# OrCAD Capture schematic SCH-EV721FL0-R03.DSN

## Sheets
1 Block Diagram
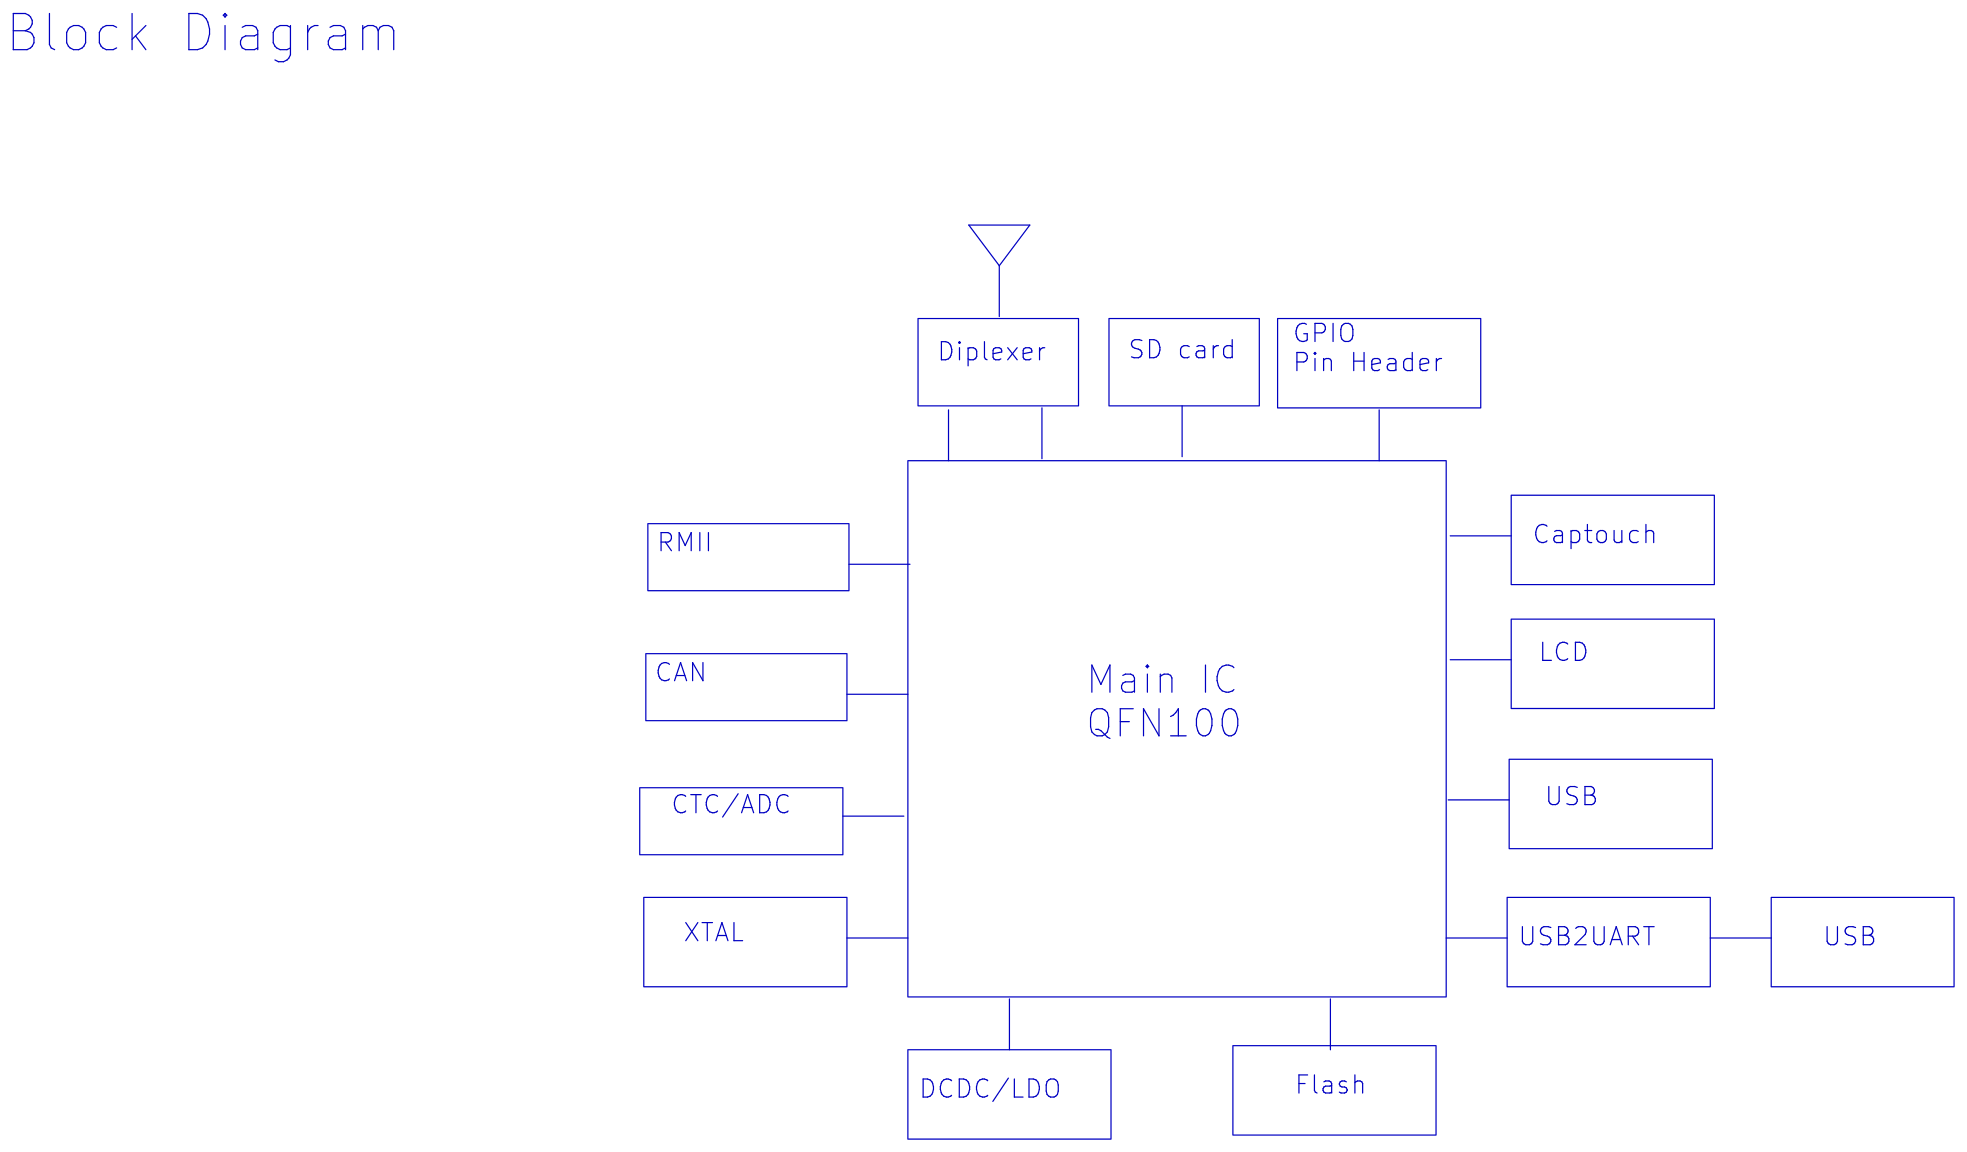
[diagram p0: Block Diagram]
2 Power Tree: title: G2; rev: 1.0; note: <>
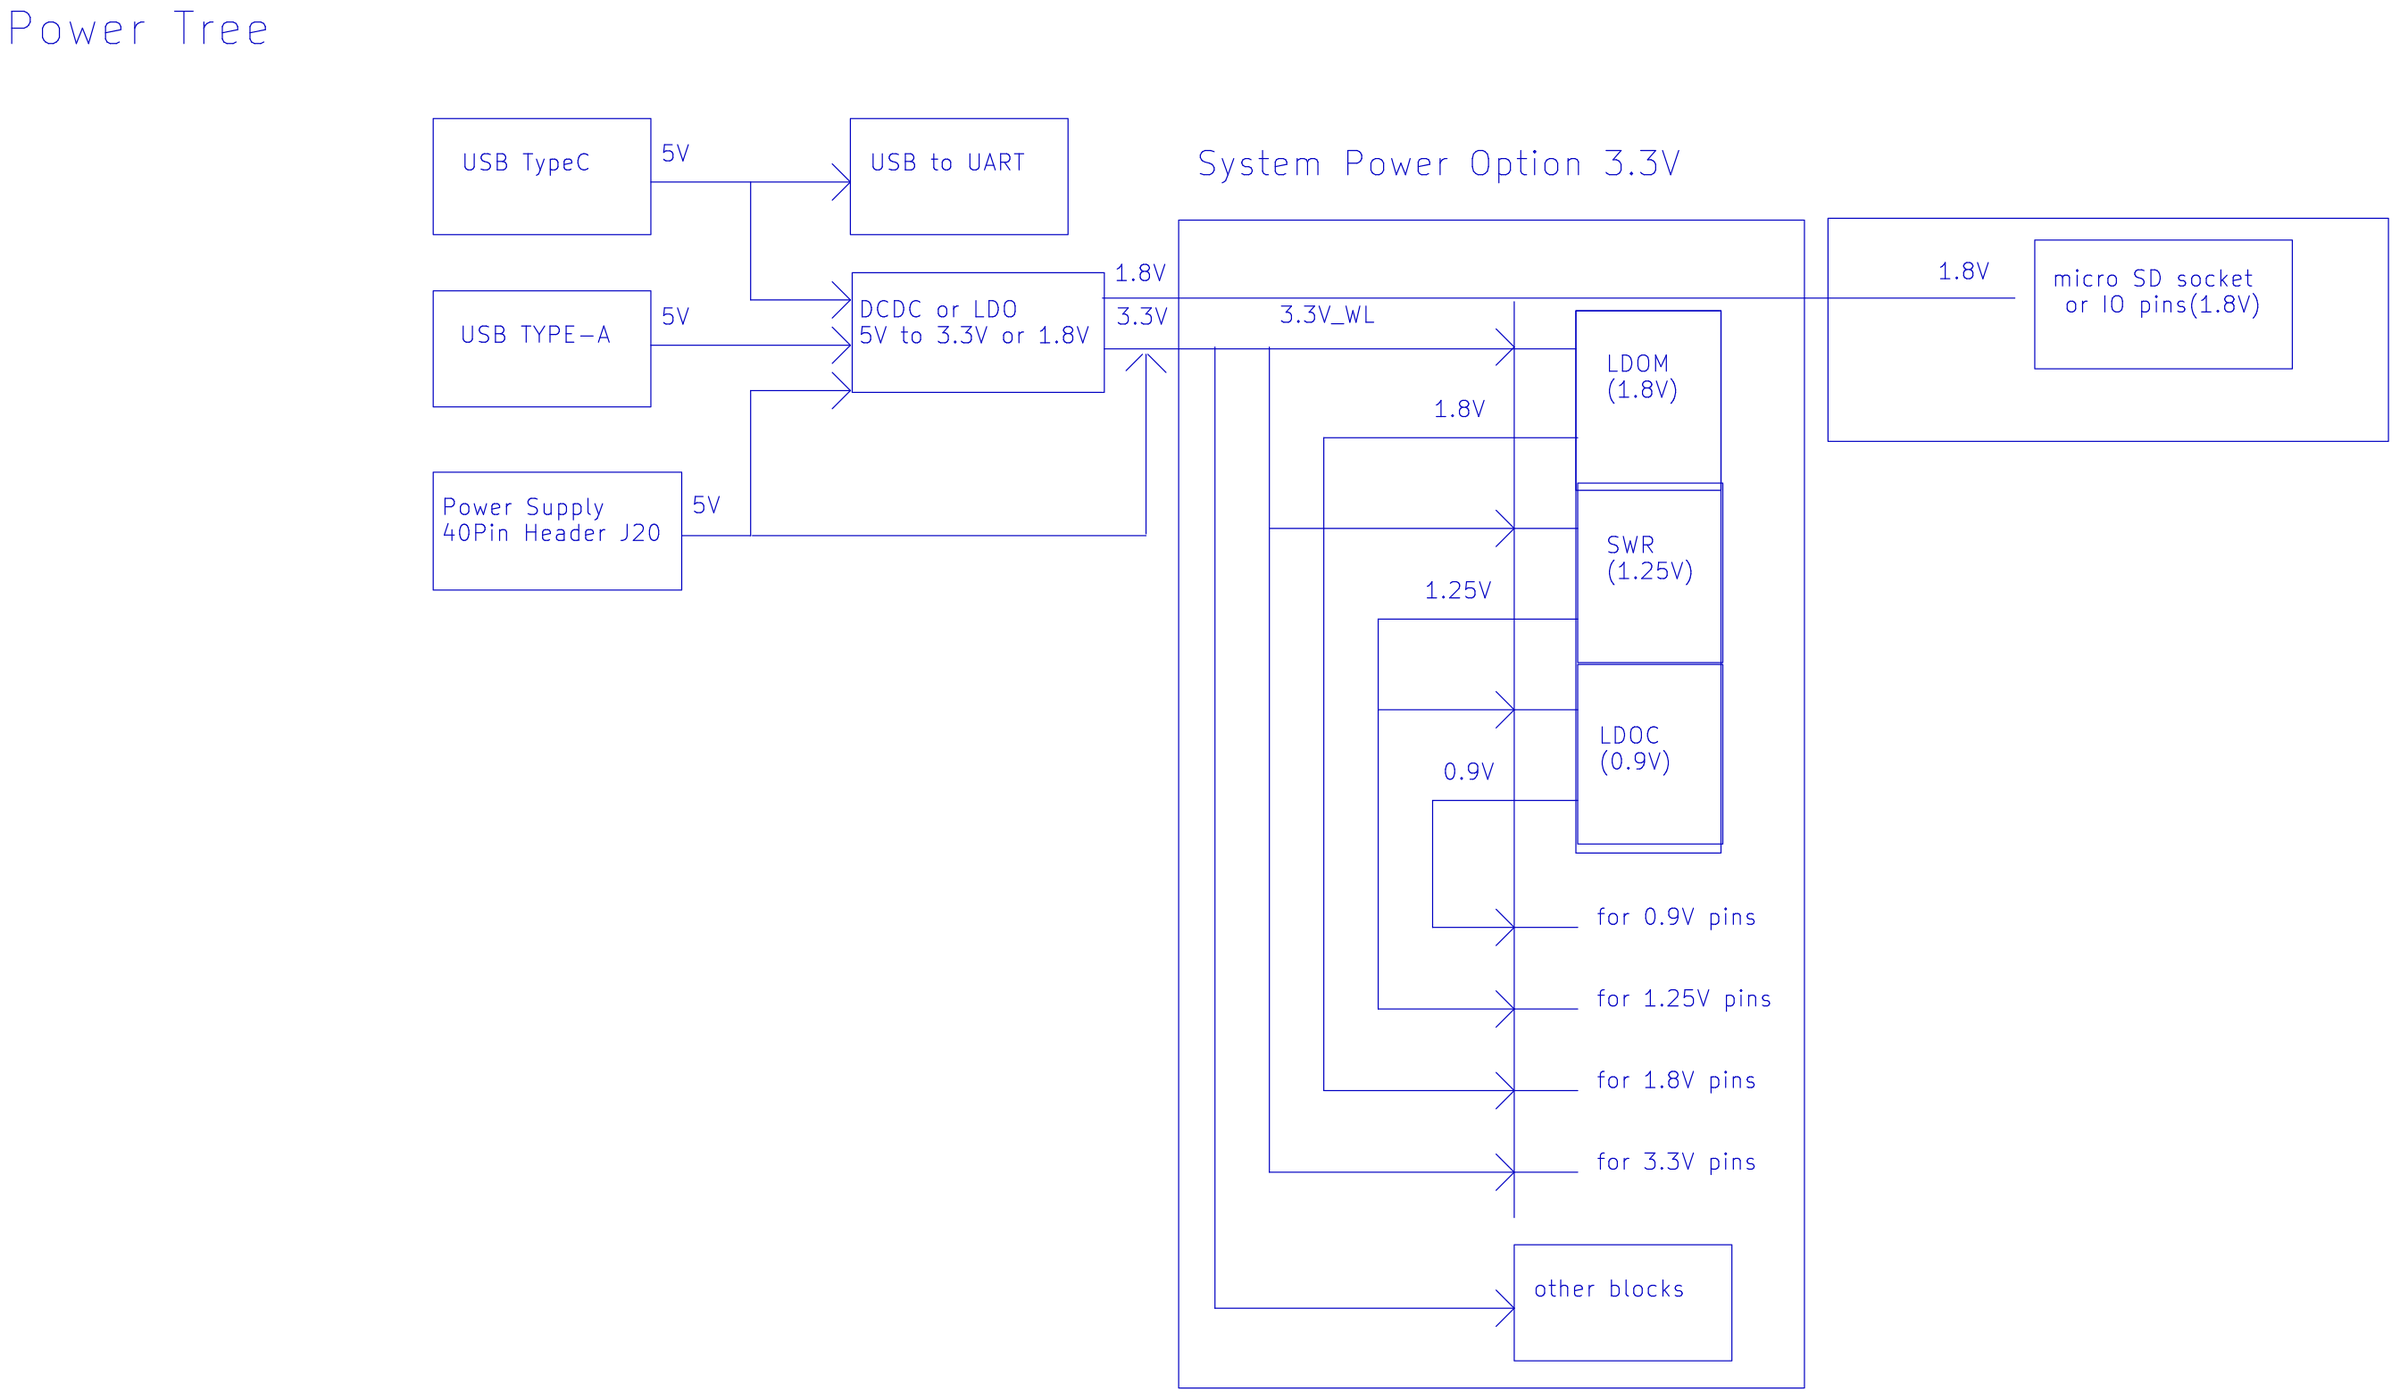
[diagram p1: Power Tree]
3 Power and USB2UART: size Custom; title: G2; rev: 1.0; note: <>
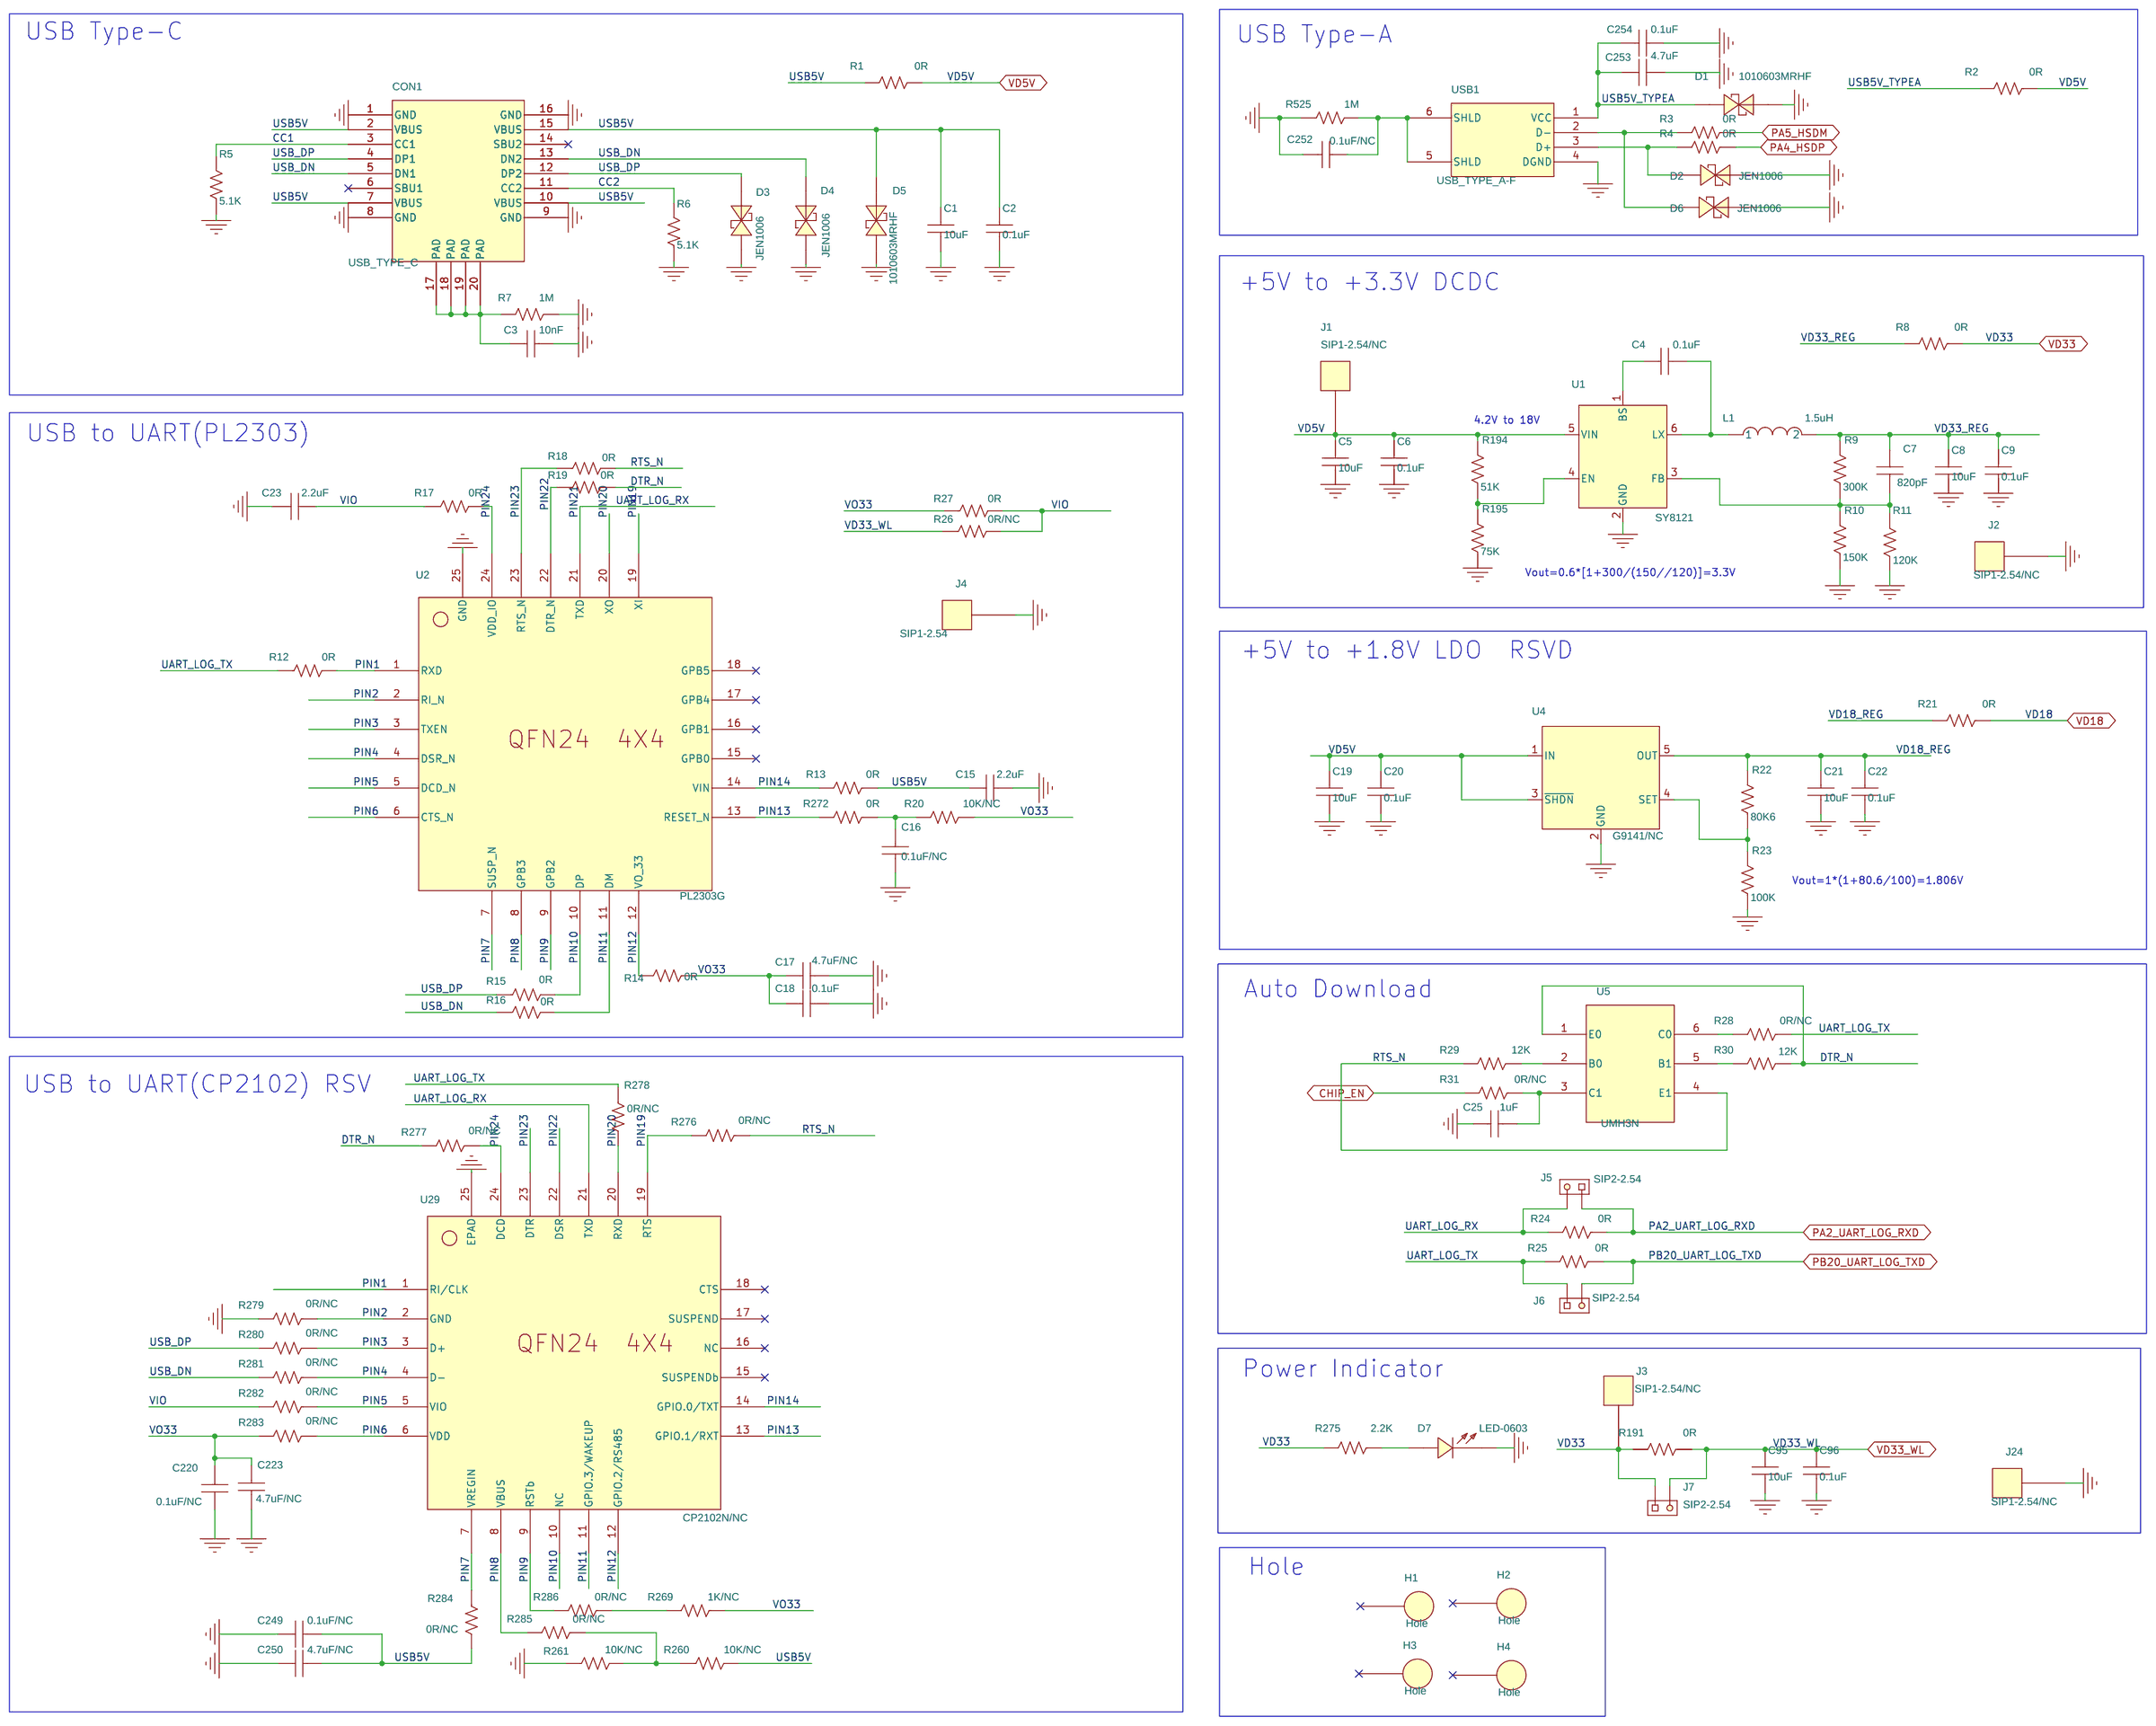
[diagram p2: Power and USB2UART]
4 Main Chip: size Custom; title: G2; rev: 1.0; note: <>
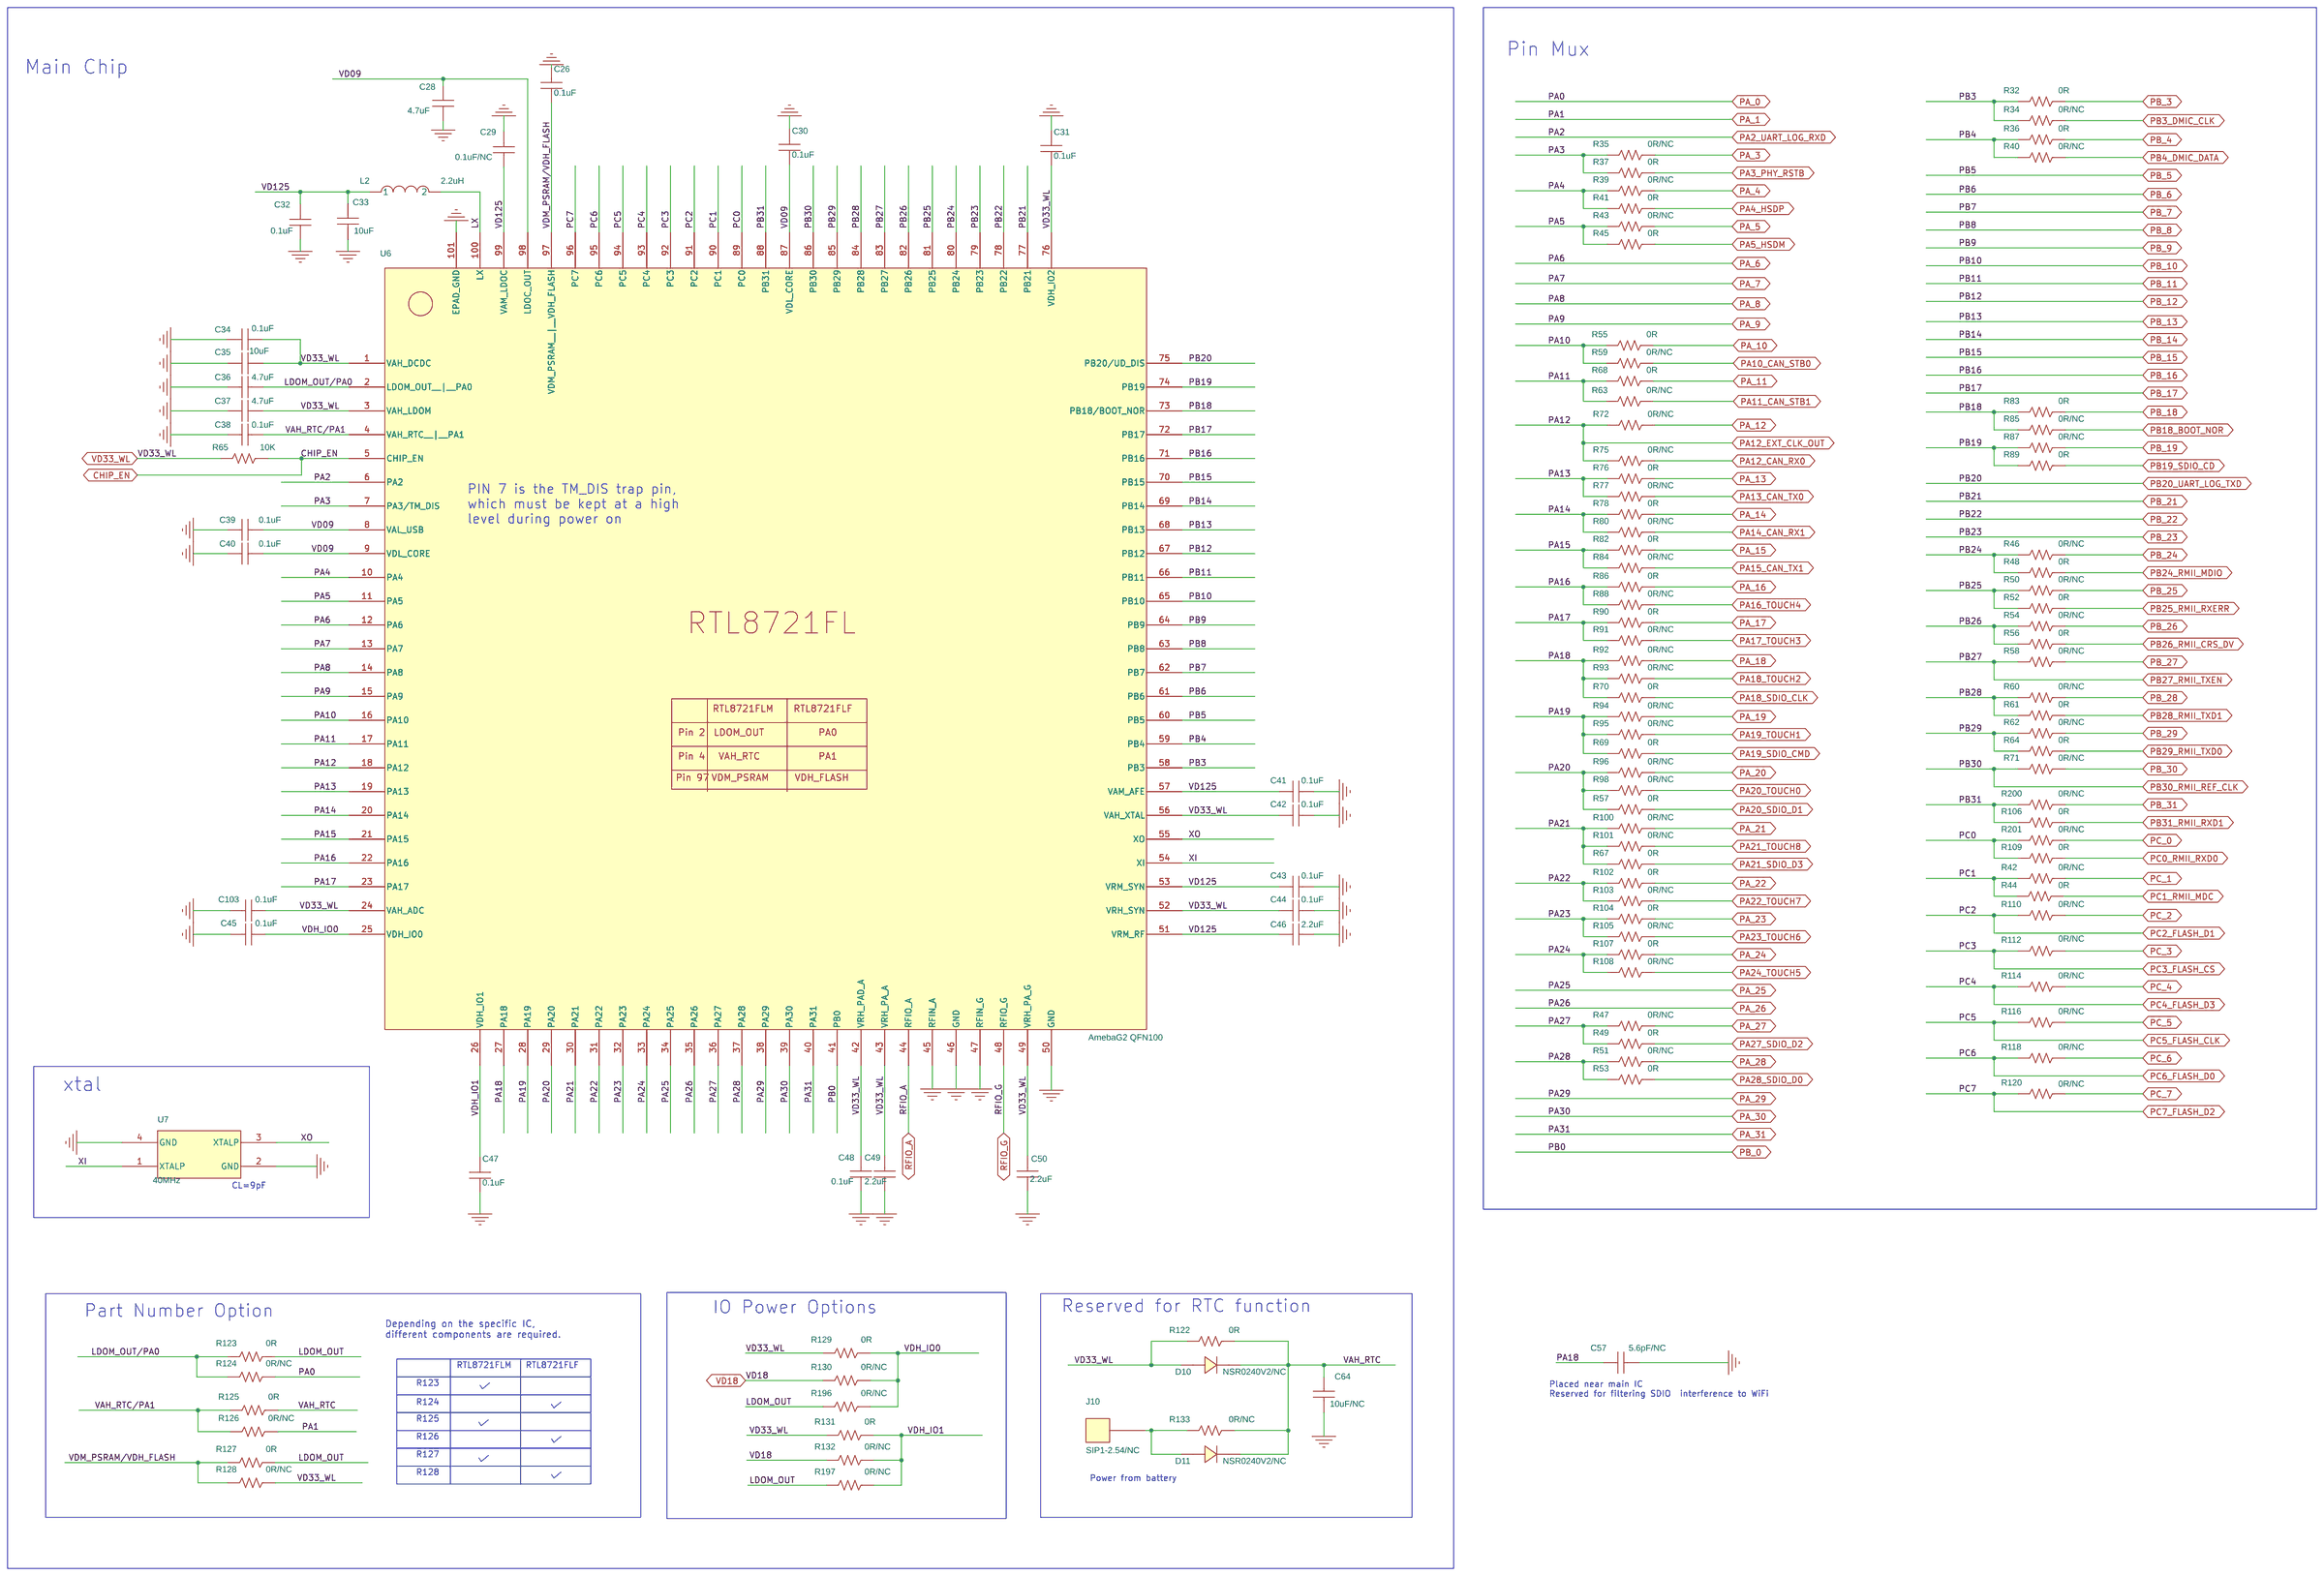
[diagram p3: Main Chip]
5 RF: size B; title: EV721DG0; rev: 1.0; note: <>
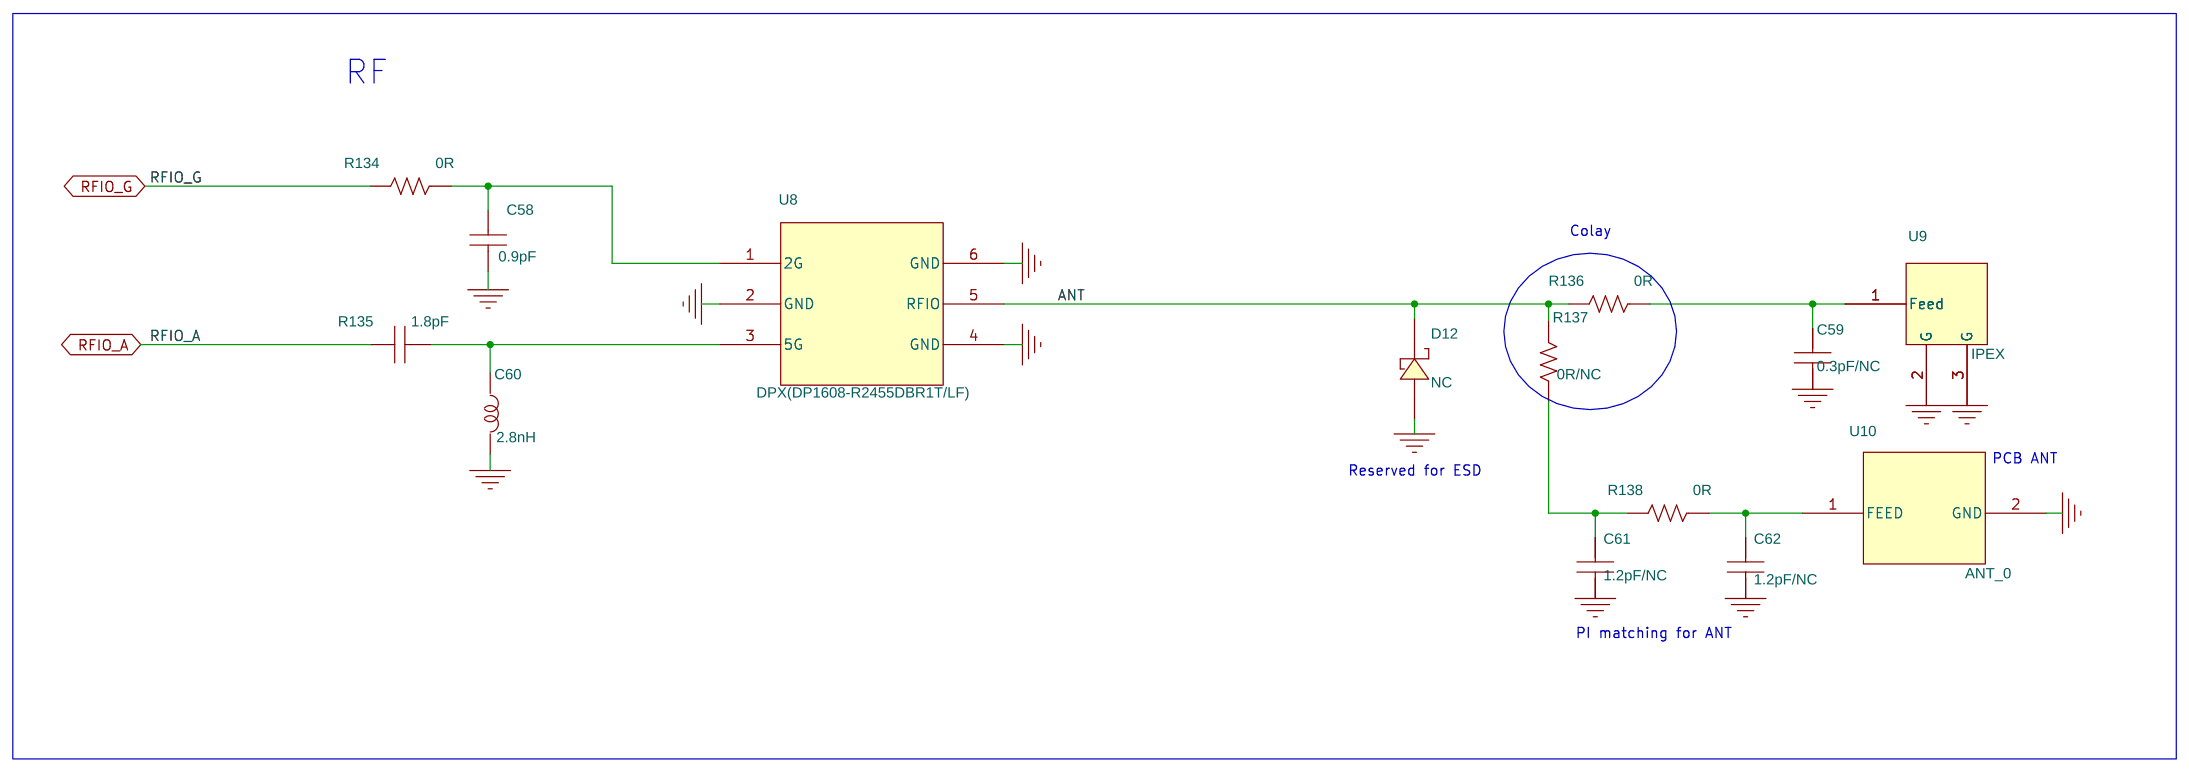
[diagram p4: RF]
6 Ethernet: size B
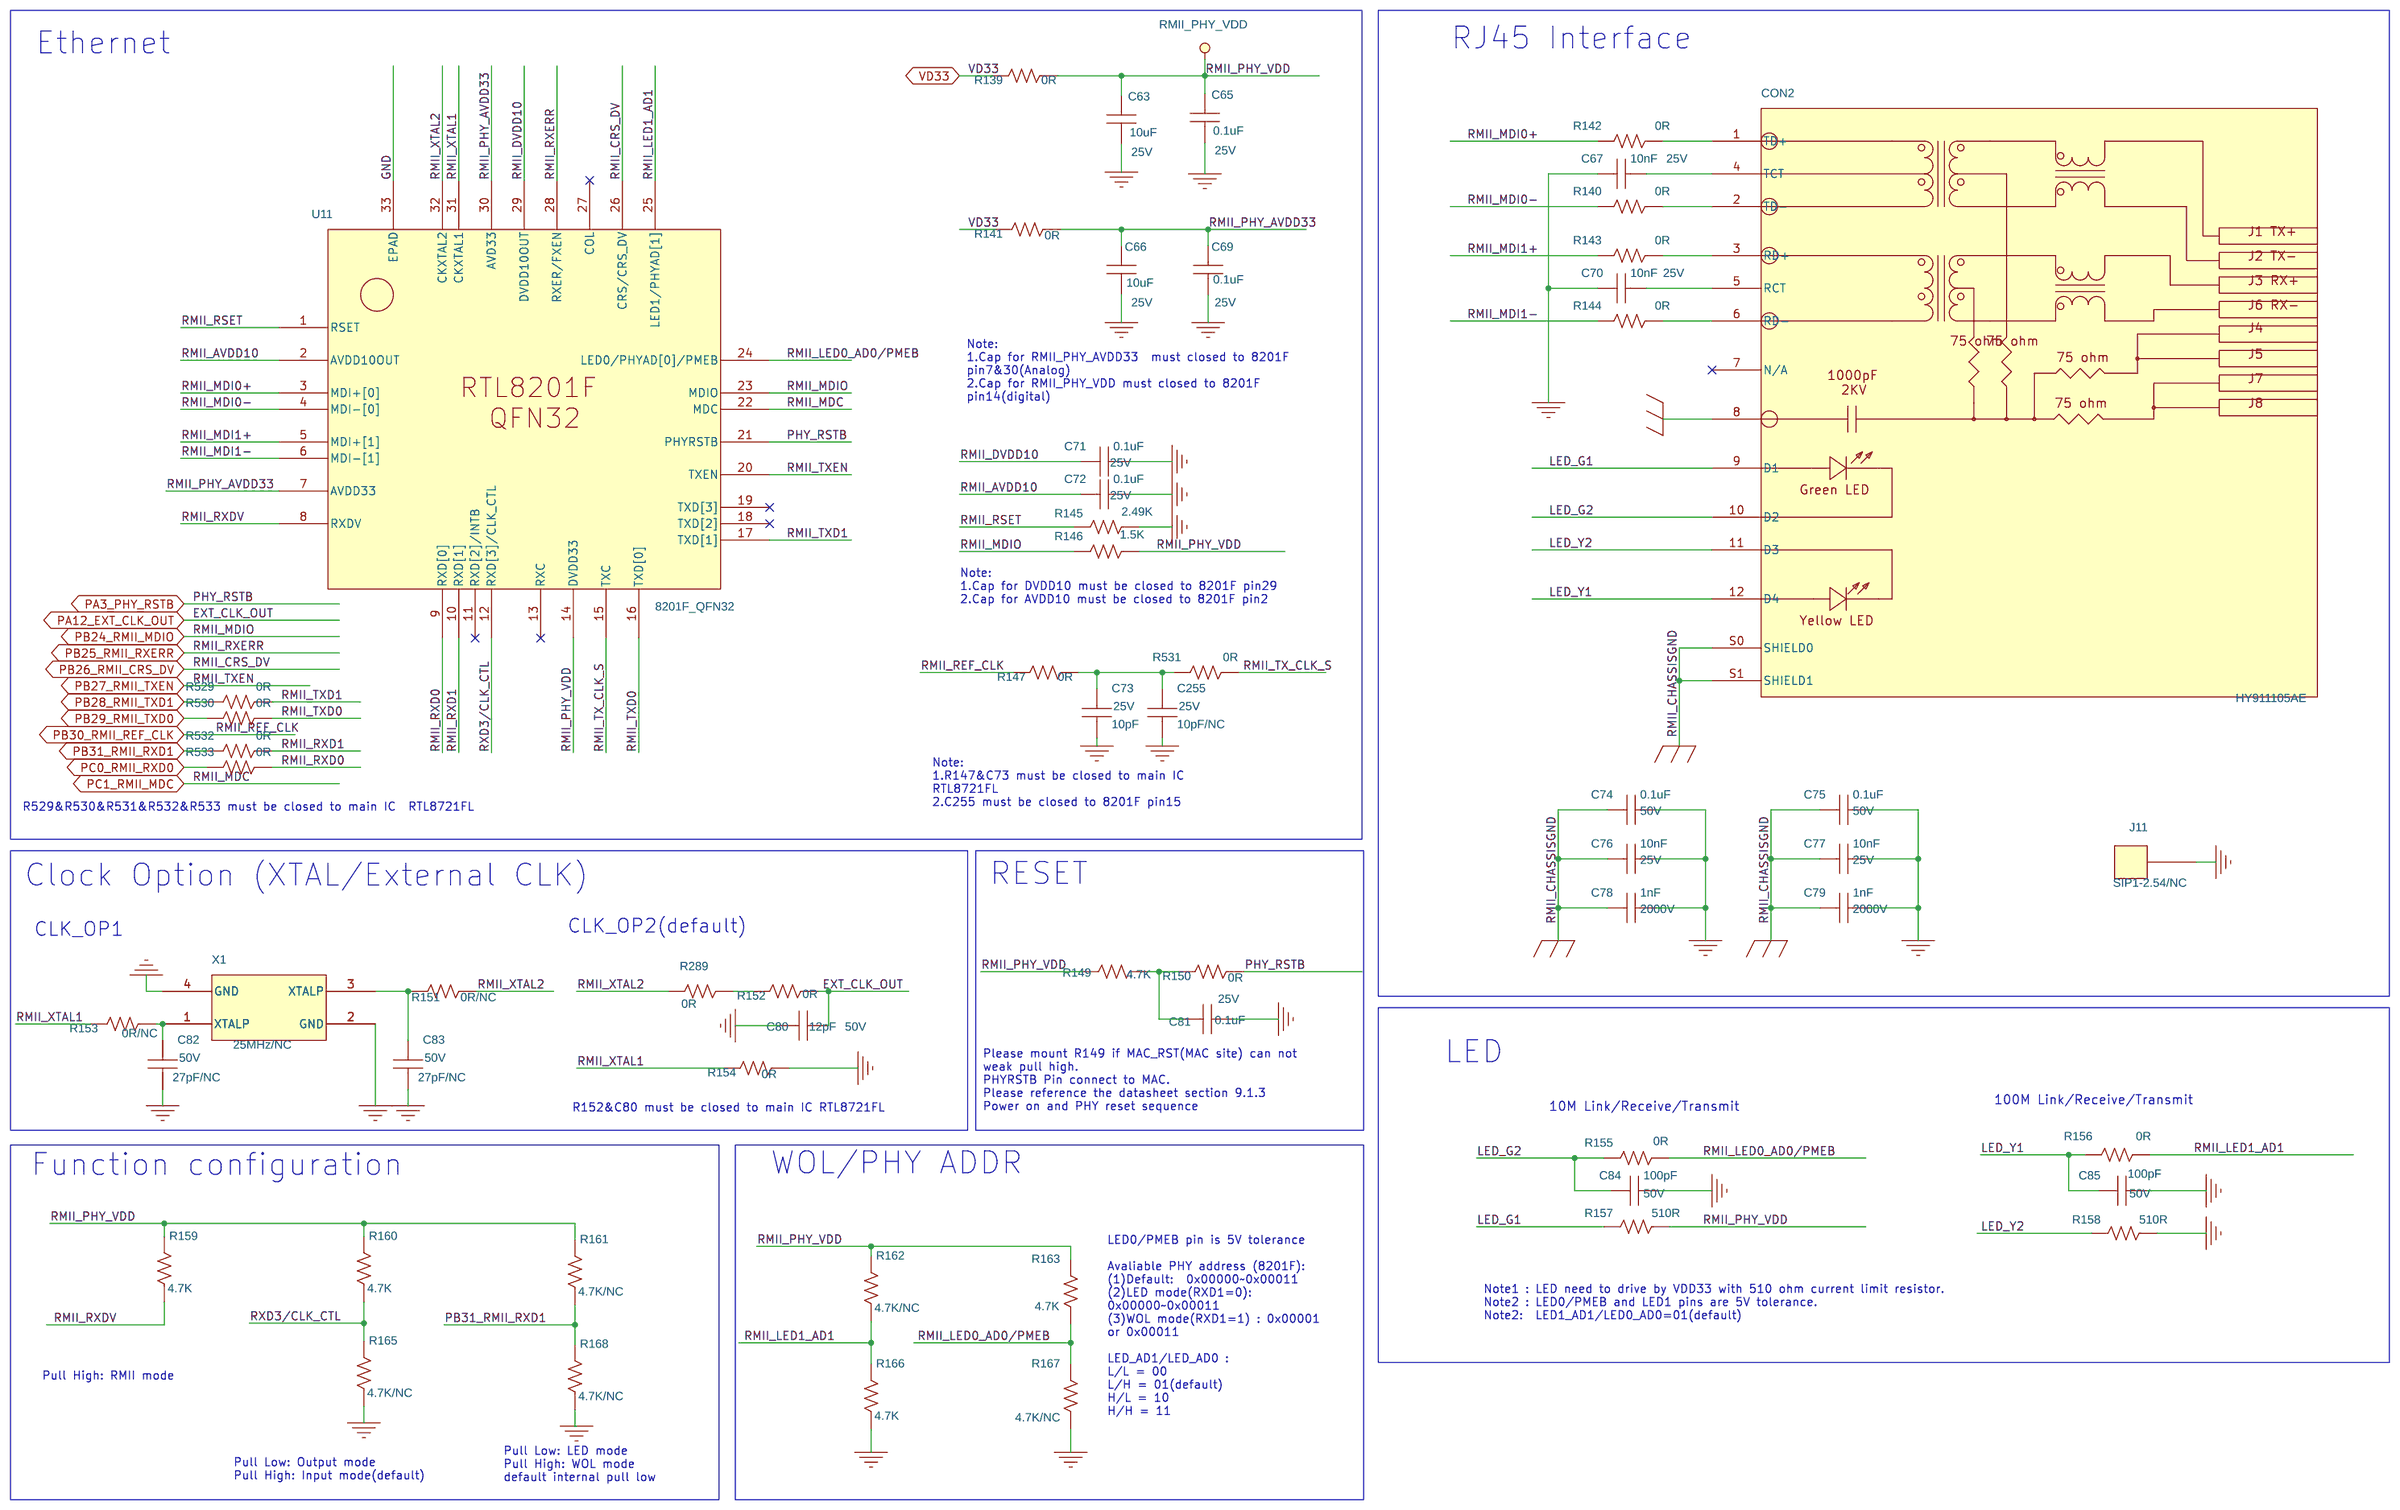
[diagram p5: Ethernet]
7 Function Block: size B; title: G2; rev: 1.0; note: <>
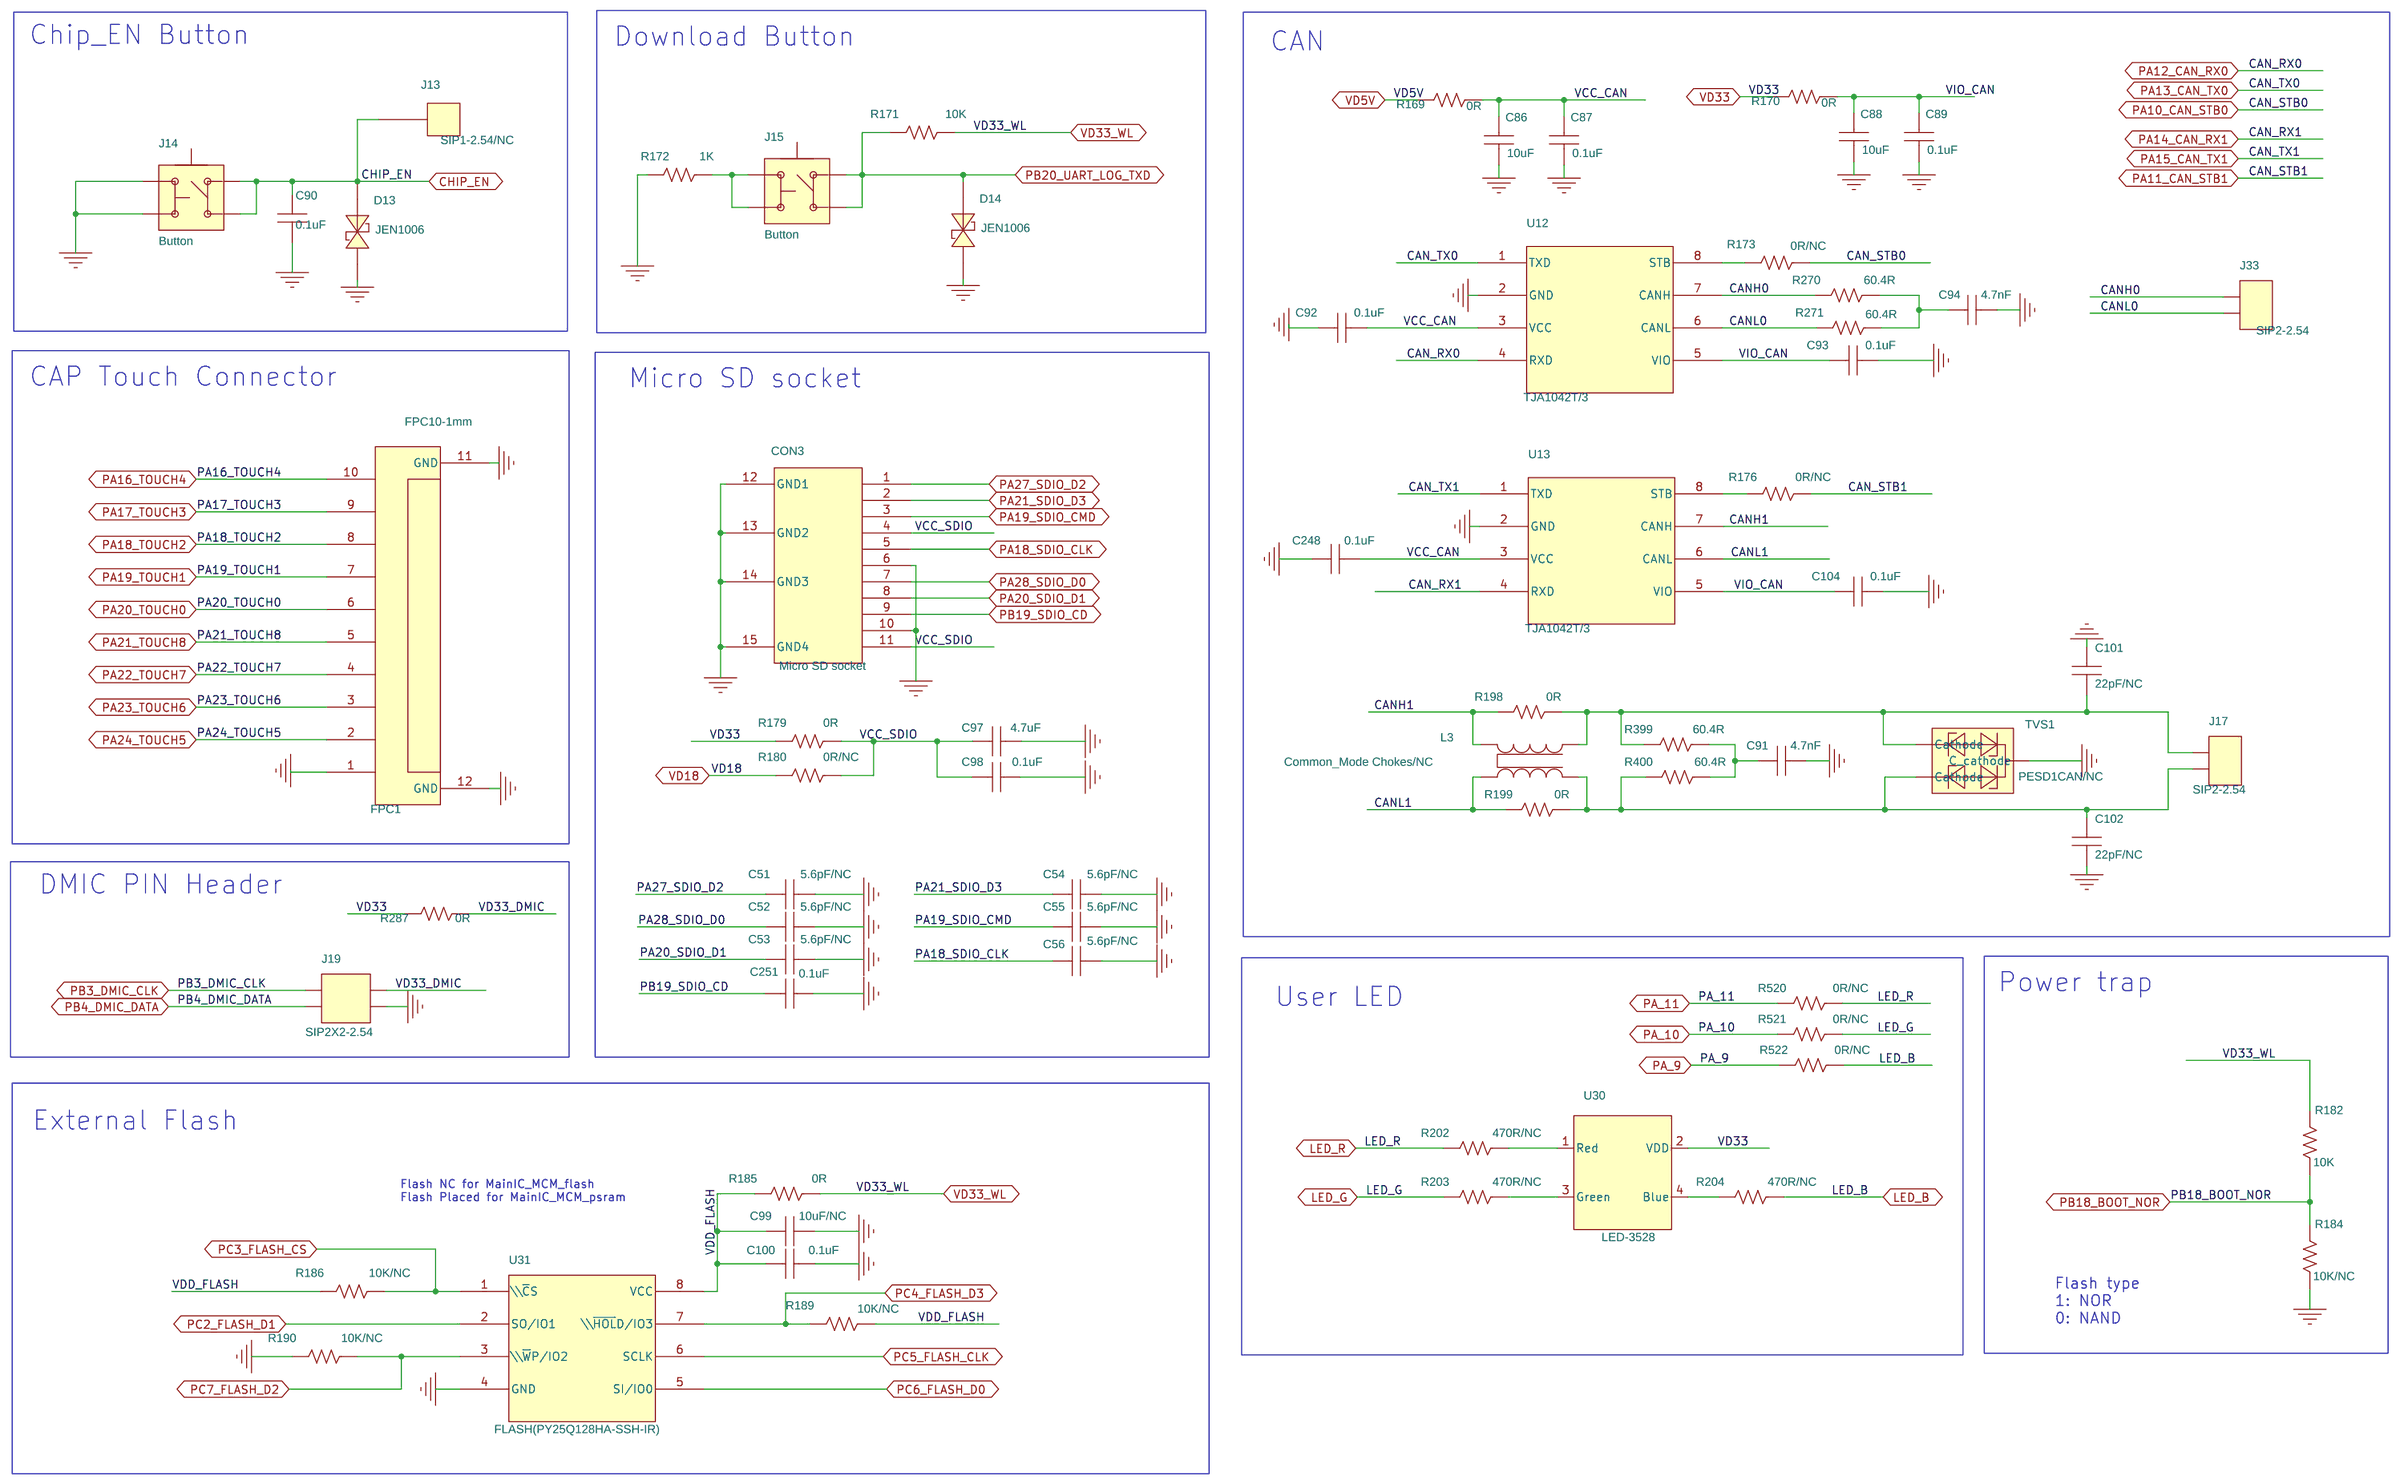
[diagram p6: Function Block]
8 Pin Header: size A; title: G2; rev: 1.0; note: <>
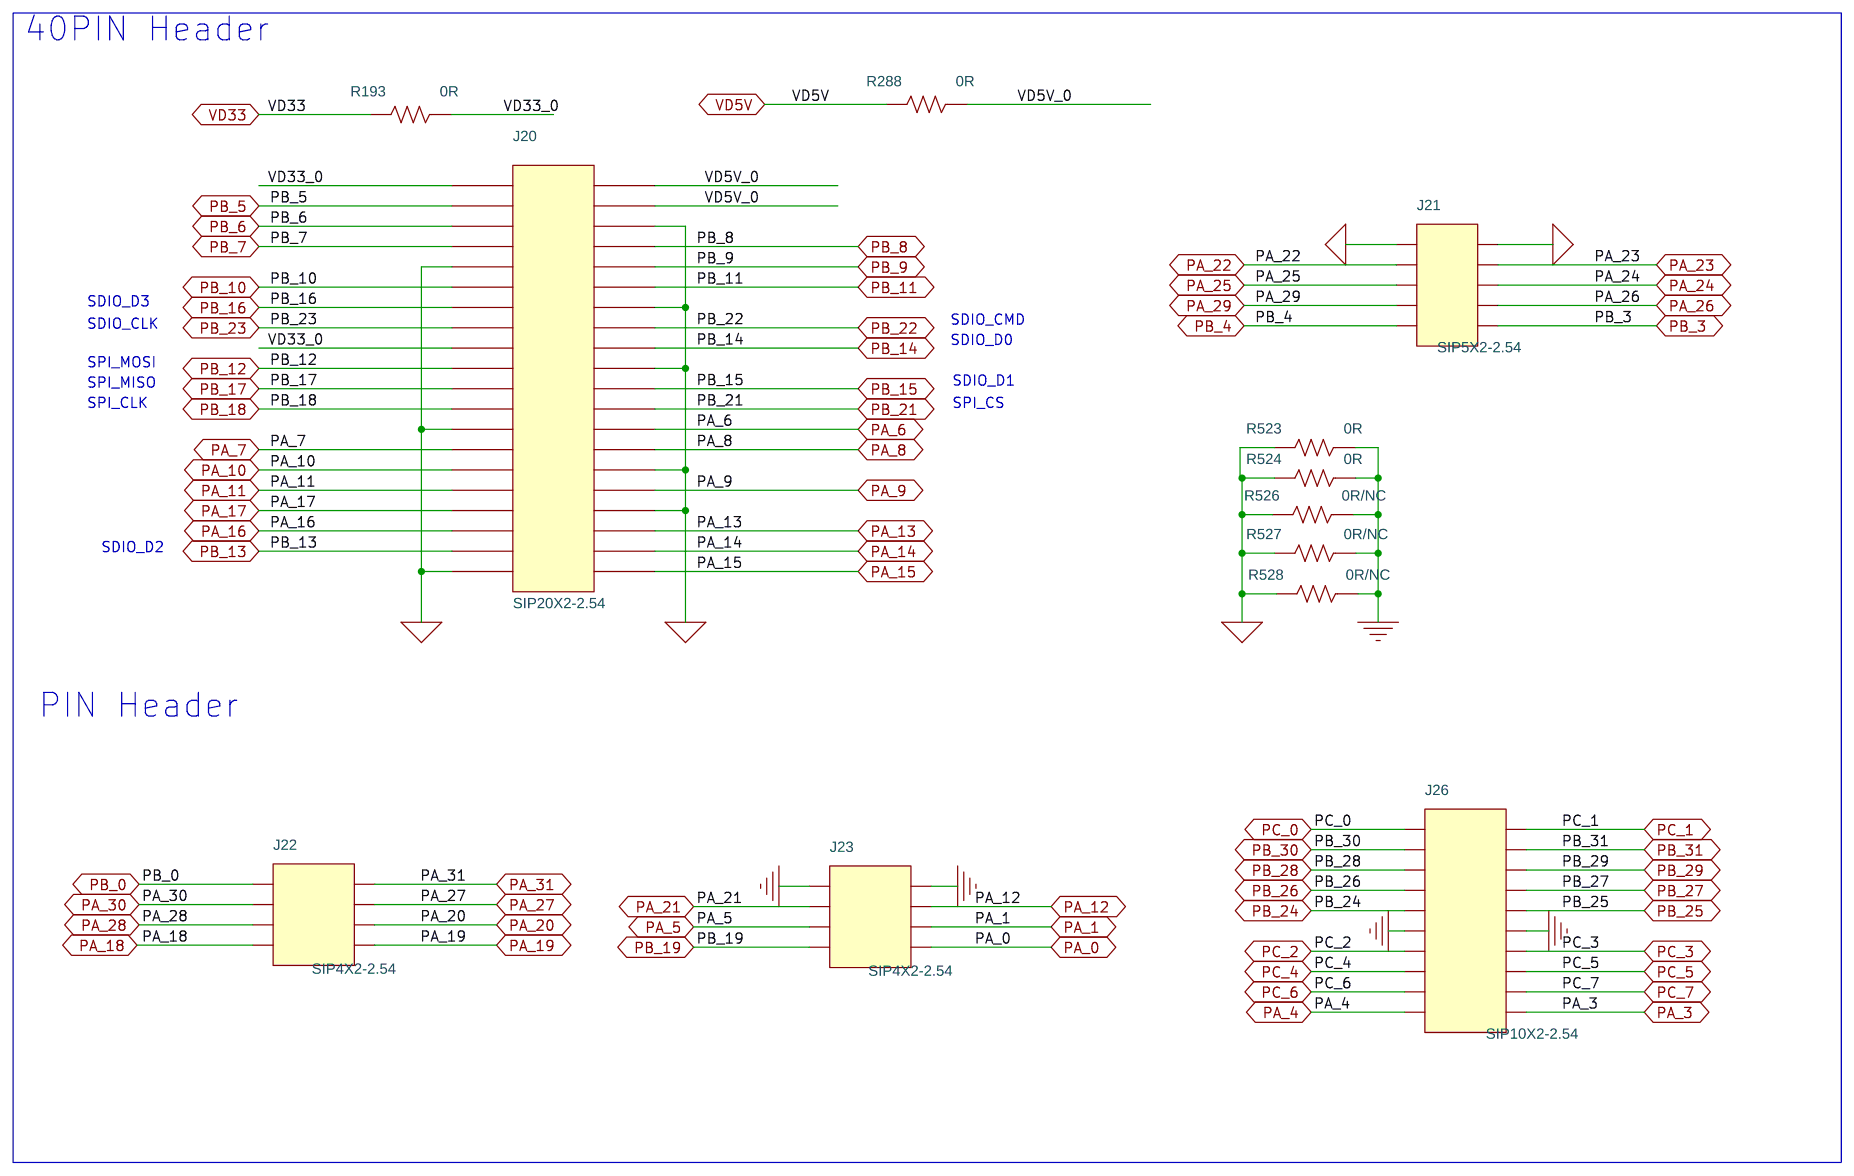
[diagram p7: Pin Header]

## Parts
sheet Ethernet
C63  10uF  [C0603]
C65  0.1uF  [C0201]
C66  10uF  [C0603]
C67  10nF  [C0402]
C69  0.1uF  [C0201]
C70  10nF  [C0402]
C71  0.1uF  [C0402]
C72  0.1uF  [C0402]
C73  10pF  [C0201]
C74  0.1uF  [C0603]
C75  0.1uF  [C0603]
C76  10nF  [C0402]
C77  10nF  [C0402]
C78  1nF  [C1206]
C79  1nF  [C1206]
C80  12pF  [C0402]
C81  0.1uF  [C0402]
C82  27pF/NC  [C0402]
C83  27pF/NC  [C0402]
C84  100pF  [C0402]
C85  100pF  [C0402]
C255  10pF/NC  [C0201]
CON2  HY911105AE  [RJ-45_1]
J11  SIP1-2.54/NC  [SIP1-2.54]
R139  0R  [R0402]
R140  0R  [R0201]
R141  0R  [R0402]
R142  0R  [R0201]
R143  0R  [R0201]
R144  0R  [R0201]
R145  2.49K  [R0402]
R146  1.5K  [R0402]
R147  0R  [R0402]
R149  4.7K  [R0402]
R150  0R  [R0402]
R151  0R/NC  [R0402]
R152  0R  [R0402]
R153  0R/NC  [R0402]
R154  0R  [R0402]
R155  0R  [R0402]
R156  0R  [R0402]
R157  510R  [R0402]
R158  510R  [R0402]
R159  4.7K  [R0402]
R160  4.7K  [R0402]
R161  4.7K/NC  [R0201]
R162  4.7K/NC  [R0402]
R163  4.7K  [R0402]
R165  4.7K/NC  [R0402]
R166  4.7K  [R0402]
R167  4.7K/NC  [R0402]
R168  4.7K/NC  [R0201]
R289  0R  [R0402]
R529  0R  [R0201]
R530  0R  [R0201]
R531  0R  [R0201]
R532  0R  [R0201]
R533  0R  [R0201]
U11  8201F_QFN32  [QFN32-0.5-5X5]
X1  25MHz/NC  [XTAL-3225]
sheet Function Block
C51  5.6pF/NC  [C0201]
C52  5.6pF/NC  [C0201]
C53  5.6pF/NC  [C0201]
C54  5.6pF/NC  [C0201]
C55  5.6pF/NC  [C0201]
C56  5.6pF/NC  [C0201]
C86  10uF  [C0603]
C87  0.1uF  [C0402]
C88  10uF  [C0603]
C89  0.1uF  [C0402]
C90  0.1uF  [C0402]
C91  4.7nF  [C0402]
C92  0.1uF  [C0402]
C93  0.1uF  [C0402]
C94  4.7nF  [C0402]
C97  4.7uF  [C0402]
C98  0.1uF  [C0402]
C99  10uF/NC  [C0402]
C100  0.1uF  [C0201]
C101  22pF/NC  [C0402]
C102  22pF/NC  [C0402]
C104  0.1uF  [C0402]
C248  0.1uF  [C0402]
C251  0.1uF  [C0201]
CON3  Micro SD socket  [SD_CARD15]
D13  JEN1006  [D0402-JEN]
D14  JEN1006  [D0402-JEN]
FPC1  FPC10-1mm  [FPC10-1]
J13  SIP1-2.54/NC  [SIP1-2.54]
J14  Button  [SW-4P-3X4]
J15  Button  [SW-4P-3X4]
J17  SIP2-2.54  [SIP2-2.54]
J19  SIP2X2-2.54  [SIP2X2-2.54]
J33  SIP2-2.54  [SIP2-2.54]
L3  Common_Mode Chokes/NC  [CMF5940]
R169  0R  [R0402]
R170  0R  [R0402]
R171  10K  [R0402]
R172  1K  [R0402]
R173  0R/NC  [R0402]
R176  0R/NC  [R0402]
R179  0R  [R0805]
R180  0R/NC  [R0805]
R182  10K  [R0402]
R184  10K/NC  [R0402]
R185  0R  [R0402]
R186  10K/NC  [R0201]
R189  10K/NC  [R0201]
R190  10K/NC  [R0201]
R198  0R  [R0402]
R199  0R  [R0402]
R202  470R/NC  [R0402]
R203  470R/NC  [R0402]
R204  470R/NC  [R0402]
R270  60.4R  [R0402]
R271  60.4R  [R0402]
R287  0R  [R0402]
R399  60.4R  [R0402]
R400  60.4R  [R0402]
R520  0R/NC  [R0402]
R521  0R/NC  [R0402]
R522  0R/NC  [R0402]
TVS1  PESD1CAN/NC  [SOT-23_MINI_S]
U12  TJA1042T/3  [SO8-150-4.9X3.9]
U13  TJA1042T/3  [SO8-150-4.9X3.9]
U30  LED-3528  [LED-3528]
U31  FLASH(PY25Q128HA-SSH-IR)  [WSON8-1.27-8X6-8pin]
sheet Main Chip
C26  0.1uF  [C0201]
C28  4.7uF  [C0402]
C29  0.1uF/NC  [C0201]
C30  0.1uF  [C0201]
C31  0.1uF  [C0201]
C32  0.1uF  [C0201]
C33  10uF  [C0402]
C34  0.1uF  [C0201]
C35  10uF  [C0402]
C36  4.7uF  [C0402]
C37  4.7uF  [C0402]
C38  0.1uF  [C0201]
C39  0.1uF  [C0201]
C40  0.1uF  [C0201]
C41  0.1uF  [C0201]
C42  0.1uF  [C0201]
C43  0.1uF  [C0201]
C44  0.1uF  [C0201]
C45  0.1uF  [C0201]
C46  2.2uF  [C0402]
C47  0.1uF  [C0201]
C48  0.1uF  [C0201]
C49  2.2uF  [C0402]
C50  2.2uF  [C0402]
C57  5.6pF/NC  [C0201]
C64  10uF/NC  [C0603]
C103  0.1uF  [C0201]
D10  NSR0240V2/NC  [SOD-X23]
D11  NSR0240V2/NC  [SOD-X23]
J10  SIP1-2.54/NC  [SIP1-2.54]
L2  2.2uH  [L2016]
R32  0R  [R0402]
R34  0R/NC  [R0402]
R35  0R/NC  [R0402]
R36  0R  [R0402]
R37  0R  [R0402]
R39  0R/NC  [R0402]
R40  0R/NC  [R0402]
R41  0R  [R0402]
R42  0R/NC  [R0402]
R43  0R/NC  [R0402]
R44  0R  [R0402]
R45  0R  [R0402]
R46  0R/NC  [R0402]
R47  0R/NC  [R0402]
R48  0R  [R0402]
R49  0R  [R0402]
R50  0R/NC  [R0402]
R51  0R/NC  [R0402]
R52  0R  [R0402]
R53  0R  [R0402]
R54  0R/NC  [R0402]
R55  0R  [R0402]
R56  0R  [R0402]
R57  0R  [R0402]
R58  0R/NC  [R0402]
R59  0R/NC  [R0402]
R60  0R/NC  [R0402]
R61  0R  [R0402]
R62  0R/NC  [R0402]
R63  0R/NC  [R0402]
R64  0R  [R0402]
R65  10K  [R0201]
R67  0R  [R0402]
R68  0R  [R0402]
R69  0R  [R0402]
R70  0R  [R0402]
R71  0R/NC  [R0402]
R72  0R/NC  [R0402]
R75  0R/NC  [R0402]
R76  0R  [R0402]
R77  0R/NC  [R0402]
R78  0R  [R0402]
R80  0R/NC  [R0402]
R82  0R  [R0402]
R83  0R  [R0402]
R84  0R/NC  [R0402]
R85  0R/NC  [R0402]
R86  0R  [R0402]
R87  0R/NC  [R0402]
R88  0R/NC  [R0402]
R89  0R  [R0402]
R90  0R  [R0402]
R91  0R/NC  [R0402]
R92  0R/NC  [R0402]
R93  0R/NC  [R0402]
R94  0R/NC  [R0402]
R95  0R/NC  [R0402]
R96  0R/NC  [R0402]
R98  0R/NC  [R0402]
R100  0R/NC  [R0402]
R101  0R/NC  [R0402]
R102  0R  [R0402]
R103  0R/NC  [R0402]
R104  0R  [R0402]
R105  0R/NC  [R0402]
R106  0R  [R0402]
R107  0R  [R0402]
R108  0R/NC  [R0402]
R109  0R  [R0402]
R110  0R/NC  [R0201]
R112  0R/NC  [R0201]
R114  0R/NC  [R0201]
R116  0R/NC  [R0201]
R118  0R/NC  [R0201]
R120  0R/NC  [R0201]
R122  0R  [R0402]
R123  0R  [R0201]
R124  0R/NC  [R0201]
R125  0R  [R0201]
R126  0R/NC  [R0201]
R127  0R  [R0201]
R128  0R/NC  [R0201]
R129  0R  [R0201]
R130  0R/NC  [R0201]
R131  0R  [R0201]
R132  0R/NC  [R0201]
R133  0R/NC  [R0402]
R196  0R/NC  [R0201]
R197  0R/NC  [R0201]
R200  0R/NC  [R0402]
R201  0R/NC  [R0402]
U6  AmebaG2 QFN100  [QFN100-0.35-10X10-EP6.1]
U7  40MHz  [XTAL-2016]
sheet Pin Header
J20  SIP20X2-2.54  [SIP20X2-2.54]
J21  SIP5X2-2.54  [SIP5X2-2.54]
J22  SIP4X2-2.54  [SIP4X2-2.54]
J23  SIP4X2-2.54  [SIP4X2-2.54]
J26  SIP10X2-2.54  [SIP10X2-2.54]
R193  0R  [R0805]
R288  0R  [R0805]
R523  0R  [R0402]
R524  0R  [R0402]
R526  0R/NC  [R0402]
R527  0R/NC  [R0402]
R528  0R/NC  [R0402]
sheet Power and USB2UART
C1  10uF  [C0603]
C2  0.1uF  [C0402]
C3  10nF  [C0402]
C4  0.1uF  [C0402]
C5  10uF  [C0603]
C6  0.1uF  [C0402]
C7  820pF  [C0402]
C8  10uF  [C0603]
C9  0.1uF  [C0402]
C15  2.2uF  [C0402]
C16  0.1uF/NC  [C0402]
C17  4.7uF/NC  [C0402]
C18  0.1uF  [C0402]
C19  10uF  [C0603]
C20  0.1uF  [C0402]
C21  10uF  [C0603]
C22  0.1uF  [C0402]
C23  2.2uF  [C0402]
C25  1uF  [C0402]
C95  10uF  [C0603]
C96  0.1uF  [C0402]
C220  0.1uF/NC  [C0402]
C223  4.7uF/NC  [C0402]
C249  0.1uF/NC  [C0402]
C250  4.7uF/NC  [C0402]
C252  0.1uF/NC  [C0402]
C253  4.7uF  [C0402]
C254  0.1uF  [C0402]
CON1  USB_TYPE_C  [USB-TYPEC-12P-SMD]
D1  1010603MRHF  [D0603-PGB]
D2  JEN1006  [D0402-JEN]
D3  JEN1006  [D0402-JEN]
D4  JEN1006  [D0402-JEN]
D5  1010603MRHF  [D0603-PGB]
D6  JEN1006  [D0402-JEN]
D7  LED-0603  [LED-0603]
H1  Hole  [HOLE-2.7X6.0-NPTH]
H2  Hole  [HOLE-2.7X6.0-NPTH]
H3  Hole  [HOLE-2.7X6.0-NPTH]
H4  Hole  [HOLE-2.7X6.0-NPTH]
J1  SIP1-2.54/NC  [SIP1-2.54]
J2  SIP1-2.54/NC  [SIP1-2.54]
J3  SIP1-2.54/NC  [SIP1-2.54]
J4  SIP1-2.54  [SIP1-2.54]
J5  SIP2-2.54  [SIP2-2.54]
J6  SIP2-2.54  [SIP2-2.54]
J7  SIP2-2.54  [SIP2-2.54]
J24  SIP1-2.54/NC  [SIP1-2.54]
L1  1.5uH  [L4442]
R1  0R  [R0805]
R2  0R  [R0805]
R3  0R  [R0402]
R4  0R  [R0402]
R5  5.1K  [R0402]
R6  5.1K  [R0402]
R7  1M  [R0402]
R8  0R  [R0805]
R9  300K  [R0402]
R10  150K  [R0402]
R11  120K  [R0402]
R12  0R  [R0402]
R13  0R  [R0402]
R14  0R  [R0402]
R15  0R  [R0402]
R16  0R  [R0402]
R17  0R  [R0402]
R18  0R  [R0402]
R19  0R  [R0402]
R20  10K/NC  [R0402]
R21  0R  [R0805]
R22  80K6  [R0402]
R23  100K  [R0402]
R24  0R  [R0402]
R25  0R  [R0402]
R26  0R/NC  [R0402]
R27  0R  [R0402]
R28  0R/NC  [R0402]
R29  12K  [R0402]
R30  12K  [R0402]
R31  0R/NC  [R0402]
R191  0R  [R0805]
R194  51K  [R0402]
R195  75K  [R0402]
R260  10K/NC  [R0402]
R261  10K/NC  [R0402]
R269  1K/NC  [R0402]
R272  0R  [R0402]
R275  2.2K  [R0402]
R276  0R/NC  [R0402]
R277  0R/NC  [R0402]
R278  0R/NC  [R0402]
R279  0R/NC  [R0402]
R280  0R/NC  [R0402]
R281  0R/NC  [R0402]
R282  0R/NC  [R0402]
R283  0R/NC  [R0402]
R284  0R/NC  [R0402]
R285  0R/NC  [R0402]
R286  0R/NC  [R0402]
R525  1M  [R0402]
U1  SY8121  [SOT-23-6]
U2  PL2303G  [UQFN24-0.5-4X4-EP1.5X1.5]
U4  G9141/NC  [SOT-23-5]
U5  UMH3N  [SOT-363-1.6]
U29  CP2102N/NC  [UQFN24-0.5-4X4-EP1.5X1.5]
USB1  USB_TYPE_A-F  [USB-TYPEA-4P-F]
sheet RF
C58  0.9pF  [C0201]
C59  0.3pF/NC  [C0201]
C60  2.8nH  [L0201]
C61  1.2pF/NC  [C0201]
C62  1.2pF/NC  [C0201]
D12  NC  [C0201]
R134  0R  [R0201]
R135  1.8pF  [C0201]
R136  0R  [R0201]
R137  0R/NC  [R0201]
R138  0R  [R0201]
U8  DPX(DP1608-R2455DBR1T/LF)  [DPX1608-6-0.5-0.25X0.6]
U9  IPEX  [IPEX3-1.35-0.7X2.2]
U10  ANT_0  [AMEBADPLUS_BGA100_EVB_ANT]

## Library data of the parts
C63 C66 C86 C88 = CAPACITOR_NON-POL_0: ±10%,25V,X5R; Manufacturer: WALSIN; Part Number: 0603X106K250CT; Voltage: 25V; Datasheet: \\172.29.17.1\cn\WLAN\WLAN2\boarddesignLIB\55_component_database\Datasheet\Capacitor\Capacitor_Walsin_MLCC.pdf
C65 C69 = CAPACITOR_NON-POL_0: ±10%,25V,X5R; Manufacturer: WALSIN; Part Number: 0201X104K250CT; Voltage: 25V; Datasheet: \\172.29.17.1\cn\WLAN\WLAN2\boarddesignLIB\05_component_database\Datasheet\Capacitor\Capacitor_Walsin_MLCC.pdf
C3 C67 C70 C76 C77 = CAPACITOR_NON-POL_0: ±10%,25V,X7R; Manufacturer: WALSIN; Part Number: 0402B103K250CT; Voltage: 25V; Datasheet: \\172.29.17.1\cn\WLAN\WLAN2\boarddesignLIB\50_component_database\Datasheet\Capacitor\Capacitor_Walsin_MLCC.pdf
C71 C72 C81 C87 C89 C92 C93 C104 C248 C252 C254 = CAPACITOR_NON-POL_0: ±10%,25V,X7R; Manufacturer: WALSIN; Part Number: 0402B104K250CT; Voltage: 25V; Datasheet: \\172.29.17.1\cn\WLAN\WLAN2\boarddesignLIB\06_component_database\Datasheet\Capacitor\Capacitor_Walsin_MLCC.pdf
C73 C255 = CAPACITOR_NON-POL_0: ±5%,25V,NPO,Y; Manufacturer: WALSIN; Part Number: 0201N100J250CT; Voltage: 25V; Datasheet: \\172.29.17.1\cn\WLAN\WLAN2\boarddesignLIB\51_component_database\Datasheet\Capacitor\Capacitor_Walsin_MLCC.pdf
C74 C75 = CAPACITOR_NON-POL_0: ±10%,50V,X7R; Manufacturer: WALSIN; Part Number: 0603B104K500CT; Voltage: 50V; Datasheet: \\172.29.17.1\cn\WLAN\WLAN2\boarddesignLIB\08_component_database\Datasheet\Capacitor\Capacitor_Walsin_MLCC.pdf
C78 C79 = CAPACITOR_NON-POL_0: ±10%,2000V,X7R; Manufacturer: WALSIN; Part Number: 1206B102K202CT; Voltage: 2000V; Datasheet: \\172.29.17.1\cn\WLAN\WLAN2\boarddesignLIB\75_component_database\Datasheet\Capacitor\Capacitor_Walsin_MLCC.pdf
C80 = CAPACITOR_NON-POL_0: ±5%,50V,NPO; Manufacturer: WALSIN; Part Number: 0402N120J500CT; Voltage: 50V; Datasheet: \\172.29.17.1\cn\WLAN\WLAN2\boarddesignLIB\61_component_database\Datasheet\Capacitor\Capacitor_Walsin_MLCC.pdf
C82 C83 = CAPACITOR_NON-POL_0: ±5%,50V,NPO; Manufacturer: WALSIN; Part Number: 0402N270J500CT; Voltage: 50V; Datasheet: \\172.29.17.1\cn\WLAN\WLAN2\boarddesignLIB\123_component_database\Datasheet\Capacitor\Capacitor_Walsin_MLCC.pdf
C84 C85 = CAPACITOR_NON-POL_0: ±5%,50V,NPO; Manufacturer: WALSIN; Part Number: 0402N101J500CT; Voltage: 50V; Datasheet: \\172.29.17.1\cn\WLAN\WLAN2\boarddesignLIB\47_component_database\Datasheet\Capacitor\Capacitor_Walsin_MLCC.pdf
CON2 = RJ-45_1: 有灯，8数据脚，百兆网络变压器; Manufacturer: HCTL; Datasheet: \\172.29.17.1\cn\WLAN\WLAN2\boarddesignLIB\01_component_database\Datasheet\Connector\RJ45 Connector__HCTL_HC911105A-M305-A.pdf
J1-J4 J11 J13 J24 = CON1: Pin Header; Part Type: Pin Header
R139 R141 R147 R150-R156 R169 R170 R173 R176 R198 R199 R289 = RES_0: JUMPER; Manufacturer: WALSIN; Part Number: WR04X000PTL; Datasheet: \\172.29.17.1\cn\WLAN\WLAN2\boarddesignLIB\01_component_database\Datasheet\Resistor\Resistor_Walsin_chipR.pdf
R140 R142-R144 = RES_0: JUMPER; Manufacturer: WALSIN; Part Number: WR02X000PTL; Datasheet: \\172.29.17.1\cn\WLAN\WLAN2\boarddesignLIB\63_component_database\Datasheet\Resistor\Resistor_Walsin_chipR.pdf
R145 = RES_0: +/-1%; Manufacturer: WALSIN; Part Number: WR04X2491FTL; Datasheet: \\172.29.17.1\cn\WLAN\WLAN2\boarddesignLIB\01_component_database\Datasheet\Resistor\Resistor_Walsin_chipR.pdf
R146 = RES_0: +/-5%; Manufacturer: WALSIN; Part Number: WR04X152 JTL; Datasheet: \\172.29.17.1\cn\WLAN\WLAN2\boarddesignLIB\01_component_database\Datasheet\Resistor\Resistor_Walsin_chipR.pdf
R149 R159-R163 R165-R168 = RES_0: +/-1%; Manufacturer: WALSIN; Part Number: WR04X4701FTL; Datasheet: \\172.29.17.1\cn\WLAN\WLAN2\boarddesignLIB\01_component_database\Datasheet\Resistor\Resistor_Walsin_chipR.pdf
R157 R158 = RES_0: +/-1%; Manufacturer: WALSIN; Part Number: WR04X5100FTL; Datasheet: \\172.29.17.1\cn\WLAN\WLAN2\boarddesignLIB\01_component_database\Datasheet\Resistor\Resistor_Walsin_chipR.pdf
R110 R112 R114 R116 R118 R120 R529-R533 = RES_0: JUMPER; Manufacturer: WALSIN; Part Number: WR02X000PTL; Datasheet: \\172.29.17.1\cn\WLAN\WLAN2\boarddesignLIB\01_component_database\Datasheet\Resistor\Resistor_Walsin_chipR.pdf
U11 = RTL8201F_QFN32: Manufacturer: Realtek; Part Number: RTL8201F
X1 = XTAL_0: 16pF，40ohms，30ppm，-40-105度; Manufacturer: 加高; Part Number: E3SB25E000909E
C51-C57 = CAPACITOR_NON-POL_0: Part Number: RF03N5R6B250CT; Part Type: Ceramic; Tolerance,Voltage,Dielectric,Lead Free(Y/N): +/-0.1pF,25V,NPO,Y; Datasheet: \\172.29.17.1\cn\WLAN\WLAN2\boarddesignLIB\164_component_database\Datasheet\Capacitor\Capacitor_Walsin_MLCC.pdf
C2 C4 C6 C9 C16 C18 C20 C22 C90 C96 C98 C220 C249 = CAPACITOR_NON-POL_0: Part Number: 0402B104K250CT; Part Type: Ceramic; Tolerance,Voltage,Dielectric,Lead Free(Y/N): ±10%,25V X7R,; Datasheet: \\172.29.17.1\cn\WLAN\WLAN2\boarddesignLIB\06_component_database\Datasheet\Capacitor\Capacitor_Walsin_MLCC.pdf
C91 C94 = CAPACITOR_NON-POL_0: ±10%,50V,X7R; Manufacturer: WALSIN; Part Number: 0402B472K500CT; Voltage: 50V; Datasheet: \\172.29.17.1\cn\WLAN\WLAN2\boarddesignLIB\144_component_database\Datasheet\Capacitor\Capacitor_Walsin_MLCC.pdf
C17 C97 = CAPACITOR_NON-POL_0: Part Number: 0402X475M160CT; Part Type: Ceramic; Tolerance,Voltage,Dielectric,Lead Free(Y/N): ±20%,16V,X5R; Datasheet: \\172.29.17.1\cn\WLAN\WLAN2\boarddesignLIB\147_component_database\Datasheet\Capacitor\Capacitor_Walsin_MLCC.pdf
C99 = CAPACITOR_NON-POL_0: Part Number: 0402X106K160CT; Voltage: 16V; Datasheet: \\172.29.17.1\cn\WLAN\WLAN2\boarddesignLIB\54_component_database\Datasheet\Capacitor\Capacitor_Walsin_MLCC.pdf
C26 C29-C32 C34 C38-C45 C47 C48 C100 C103 C251 = CAPACITOR_NON-POL_0: Part Number: 0201X104K100CT; Part Type: Ceramic; Tolerance,Voltage,Dielectric,Lead Free(Y/N): ±10%，10V，X5R; Datasheet: \\172.29.17.1\cn\WLAN\WLAN2\boarddesignLIB\04_component_database\Datasheet\Capacitor\Capacitor_Walsin_MLCC.pdf
C101 C102 = CAPACITOR_NON-POL_0: ±5%,50V,NPO; Manufacturer: WALSIN; Part Number: 0402N220J500CT; Voltage: 50V; Datasheet: \\172.29.17.1\cn\WLAN\WLAN2\boarddesignLIB\112_component_database\Datasheet\Capacitor\Capacitor_Walsin_MLCC.pdf
CON3 = SD-TF21: SD Connector 15PIN; Part Number: SD-TF21-406-S157
D2-D4 D6 D13 D14 = Bi-directional_ESD_0: Bi-directional, 3.3V; Manufacturer: JDT Fuse; Part Number: JEN1006-3.3V-ULC; Datasheet: \\172.29.17.1\cn\WLAN\WLAN2\boarddesignLIB\01_component_database\Datasheet\TVS\TVS_JDTfuse_JEN1006-3.3V-ULC.pdf
FPC1 = FPC-10: 单排，1．0mm-10P.下接翻盖
J14 J15 = BUTTON_0: SMD, 4pin， -25℃ to 70℃; Part Number: TSA343G00-250DZY; Part Type: Tactile Switch; Datasheet: \\172.29.17.1\cn\WLAN\WLAN2\boarddesignLIB\01_component_database\Datasheet\Key-Switch\Key_Bright, TSA343G00-250DZY.pdf
J17 J33 = CON2: Pin Header
J19 = CON4A: Pin Header
L3 = Common_chokes_0: 4P,150℃; Manufacturer: TDK; Part Number: B82789C0/S0; Datasheet: \\172.29.17.1\cn\WLAN\WLAN2\boarddesignLIB\01_component_database\Datasheet\Bead-EMI Optimization\Common_mode_Chokes_TDK_ B82789C0.pdf
R171 = RES_0: Part Number: WR04X1002 FTL; Part type: Chip Resistor; Tolerance,Voltage,Dielectric,Lead Free(Y/N): +/-1%; Datasheet: \\172.29.17.1\cn\WLAN\WLAN2\boarddesignLIB\190_component_database\Datasheet\ResistorResistor_Walsin, chipR.pdf
R172 = RES_0: Part Number: WR04X1001FTL; Part type: Chip Resistor; Tolerance,Voltage,Dielectric,Lead Free(Y/N): +/-1%; Datasheet: \\172.29.17.1\cn\WLAN\WLAN2\boarddesignLIB\153_component_database\Datasheet\ResistorResistor_Walsin, chipR.pdf
R1 R2 R8 R21 R179 R180 R191 R193 R288 = RES_0: Part Number: WR08X000PTL; Part type: Chip Resistor; Tolerance,Voltage,Dielectric,Lead Free(Y/N): JUMPER; Datasheet: \\172.29.17.1\cn\WLAN\WLAN2\boarddesignLIB\65_component_database\Datasheet\ResistorResistor_Walsin_chipR.pdf
R182 R184 = RES_0: Part Number: WR04X1002 FTL; Part type: Chip Resistor; Tolerance,Voltage,Dielectric,Lead Free(Y/N): +/-1%; Datasheet: \\172.29.17.1\cn\WLAN\WLAN2\boarddesignLIB\191_component_database\Datasheet\Resistor\Resistor_Walsin_chipR.pdf
R122 R133 R185 R287 = RES_0: Part Number: WR04X000PTL; Tolerance,Voltage,Dielectric,Lead Free(Y/N): JUMPER; Datasheet: \\172.29.17.1\cn\WLAN\WLAN2\boarddesignLIB\64_component_database\Datasheet\Resistor\Resistor_Walsin_chipR.pdf
R186 R189 R190 = RES_0: Part Number: WR02X103 JAL; Tolerance,Voltage,Dielectric,Lead Free(Y/N): +/-5%; Datasheet: \\172.29.17.1\cn\WLAN\WLAN2\boarddesignLIB\40_component_database\Datasheet\Resistor\Resistor_Walsin_chipR.pdf
R202-R204 = RES_0: Part Number: WR04X471 JTL; Tolerance,Voltage,Dielectric,Lead Free(Y/N): +/-5%; Datasheet: \\172.29.17.1\cn\WLAN\WLAN2\boarddesignLIB\141_component_database\Datasheet\Resistor\Resistor_Walsin_chipR.pdf
R270 R271 R399 R400 = RES_0: +/-1%; Manufacturer: WALSIN; Part Number: WR04X60R4FTL; Datasheet: \\172.29.17.1\cn\WLAN\WLAN2\boarddesignLIB\01_component_database\Datasheet\Resistor\Resistor_Walsin_chipR.pdf
R3 R4 R12-R19 R24-R28 R31 R32 R34-R37 R39-R64 R67-R72 R75-R78 R80 R82-R96 R98 R100-R109 R200 R201 R272 R276-R286 R520-R524 R526-R528 = RES_0: Part Number: WR04X000PTL; Part type: Chip Resistor; Tolerance,Voltage,Dielectric,Lead Free(Y/N): JUMPER; Datasheet: \\172.29.17.1\cn\WLAN\WLAN2\boarddesignLIB\63_component_database\Datasheet\ResistorResistor_Walsin_chipR.pdf
TVS1 = CAN_ESD_0: 23Kv, Can bus ESD; Manufacturer: Nexperia; Part Number: PESD1CAN; Datasheet: \\172.29.17.1\cn\WLAN\WLAN2\boarddesignLIB\01_component_database\Datasheet\TVS\ESD_Nexperia_PESD1CAN.pdf
U12 U13 = CAN_trans_0: ±8Kv; Datasheet: \\172.29.17.1\cn\WLAN\WLAN2\boarddesignLIB\01_component_database\Datasheet\Communicaton Interface Chip\CAN transceiver_NXP_TJA1042T3.pdf
U30 = LED_1: SMT LED; Part Number: S3528EHMRGBTP-H5-D; Part Type: LED; Datasheet: \\172.29.17.1\cn\WLAN\WLAN2\boarddesignLIB\01_component_database\Datasheet\Optocoupler-LED-Photoelectric DeviceLED_Inbright, S3528EHMRGBTP-H5-D 3528RGB.pdf
U31 = Flash_0: 1 E-Pad; Part Number: FLASH
C28 C36 C37 = CAPACITOR_NON-POL_0: Part Number: 0402X475M160CT; Tolerance,Voltage,Dielectric,Lead Free(Y/N): ±20%,16V,X5R; Voltage: 16V; Datasheet: \\172.29.17.1\cn\WLAN\WLAN2\boarddesignLIB\147_component_database\Datasheet\Capacitor\Capacitor_Walsin_MLCC.pdf
C33 C35 = CAPACITOR_NON-POL_0: ±10%,16V,X5R; Manufacturer: WALSIN; Part Number: 0402X106K160CT; Voltage: 16V; Datasheet: \\172.29.17.1\cn\WLAN\WLAN2\boarddesignLIB\54_component_database\Datasheet\Capacitor\Capacitor_Walsin_MLCC.pdf
C15 C23 C46 C49 C50 = CAPACITOR_NON-POL_0: Part Number: 0402X225K250CT; Part Type: Ceramic; Tolerance,Voltage,Dielectric,Lead Free(Y/N): ±10%,25V,X5R; Datasheet: \\172.29.17.1\cn\WLAN\WLAN2\boarddesignLIB\93_component_database\Datasheet\Capacitor\Capacitor_Walsin_MLCC.pdf
C64 = CAPACITOR_NON-POL_0: Part Number: 0603X106K250CT; Voltage: 25V; Datasheet: \\172.29.17.1\cn\WLAN\WLAN2\boarddesignLIB\55_component_database\Datasheet\Capacitor\Capacitor_Walsin_MLCC.pdf
D10 D11 = DIODE_1: 兼容封装SOD123、S0D323、SOD523; Part Number: NSR0240V2; Datasheet: \\172.29.17.1\cn\WLAN\WLAN2\boarddesignLIB\01_component_database\Datasheet\Diode\Diode_Onsemi_NSR0240V2.pdf
J10 = CON1: Pin Header
L2 = Inductor_Power: Part Number: MAKK2016T2R2M; Part Type: Power Inductor; Õ`²îÖµTolerance(nH/%),Q‚Ž(min): ±20%
R65 = RES_0: Part Number: WR02X103 JAL; Part type: Chip Resistor; Tolerance,Voltage,Dielectric,Lead Free(Y/N): +/-5%; Datasheet: \\172.29.17.1\cn\WLAN\WLAN2\boarddesignLIB\39_component_database\Datasheet\ResistorResistor_Walsin, chipR.pdf
R123-R132 R134 R136-R138 R196 R197 = RES_0: Part Number: WR02X000PTL; Part type: Chip Resistor; Tolerance,Voltage,Dielectric,Lead Free(Y/N): JUMPER; Datasheet: \\172.29.17.1\cn\WLAN\WLAN2\boarddesignLIB\62_component_database\Datasheet\ResistorResistor_Walsin_chipR.pdf
U6 = RL7005_QFN100_2: RL7005 QFN100; Manufacturer: Realtek
U7 = XTAL_0: 9pF，25ohms，10ppm，-55-125度; Manufacturer: HOSONIC; Part Number: E1SB40E00090FE; Datasheet: \\172.29.17.1\cn\WLAN\WLAN2\boarddesignLIB\01_component_database\Datasheet\XTAL-Resonator\XTAL-40M_Hosonic_E1SB40E00090FE  2016 9pF V1.01.pdf
J20 = CON40A: Pin Header; Part Type: Pin Header
J21 = CON10A: Pin Header
J22 J23 = CON8A: Pin Header
J26 = CON20A: Pin Header
C1 C5 C8 C19 C21 C95 = CAPACITOR_NON-POL_0: Part Number: 0603X106K250CT; Part Type: Ceramic; Tolerance,Voltage,Dielectric,Lead Free(Y/N): ±10%,25V,X5R; Datasheet: \\172.29.17.1\cn\WLAN\WLAN2\boarddesignLIB\55_component_database\Datasheet\Capacitor\Capacitor_Walsin_MLCC.pdf
C7 = CAPACITOR_NON-POL_0: ±10%,50V,X7R; Manufacturer: WALSIN; Part Number: 0402B821K500CT; Voltage: 50V; Datasheet: \\172.29.17.1\cn\WLAN\WLAN2\boarddesignLIB\193_component_database\Datasheet\Capacitor\Capacitor_Walsin_MLCC.pdf
C25 = CAPACITOR_NON-POL_0: Part Number: 0402X105K250CT; Part Type: Ceramic; Tolerance,Voltage,Dielectric,Lead Free(Y/N): ±10%,25V,X5R; Datasheet: \\172.29.17.1\cn\WLAN\WLAN2\boarddesignLIB\84_component_database\Datasheet\Capacitor\Capacitor_Walsin_MLCC.pdf
C223 C250 = CAPACITOR_NON-POL_0: ±20%,16V,X5R; Manufacturer: WALSIN; Part Number: 0402X475M160CT; Voltage: 16V; Datasheet: \\172.29.17.1\cn\WLAN\WLAN2\boarddesignLIB\147_component_database\Datasheet\Capacitor\Capacitor_Walsin_MLCC.pdf
C253 = CAPACITOR_NON-POL_0: ±20%,25V,X5R; Manufacturer: WALSIN; Part Number: 0402X475M250CT; Voltage: 25V; Datasheet: \\172.29.17.1\cn\WLAN\WLAN2\boarddesignLIB\199_component_database\Datasheet\Capacitor\Capacitor_Walsin_MLCC.pdf
CON1 = USB_TYPE_C_0: TYPE C 16 PIN TOP MOUNT SMT; Part Number: 2171790001; Part Type: USB Connector; Datasheet: \\172.29.17.1\cn\WLAN\WLAN2\boarddesignLIB\01_component_database\Datasheet\Connector\Type-C_Molex, 2171790001_sd.pdf
D1 D5 = Bi-directional_ESD_0: Bi-directional, 8KV; Manufacturer: LittleFuse; Part Number: PGB1010603; Datasheet: \\172.29.17.1\cn\WLAN\WLAN2\boarddesignLIB\01_component_database\Datasheet\TVS\TVS_Littlefuse_101060.pdf
D7 = LED_0: SMT LED; Part Type: LED
H1-H4 = HOLE_0: Hole NPTH
J5-J7 = HEADER2_0: Pin Header; Part Type: Pin Header
L1 = INDUCTOR_POWER: Part Number: MWSA0402-1R5MT; Part Type: Power Inductor; Õ`²îÖµTolerance(nH/%),Q‚Ž(min): 3A,±20%
R5 R6 = RES_0: Part Number: WR04X5101FTL; Part type: Chip Resistor; Tolerance,Voltage,Dielectric,Lead Free(Y/N): +/-1%; Datasheet: \\172.29.17.1\cn\WLAN\WLAN2\boarddesignLIB\179_component_database\Datasheet\ResistorResistor_Walsin, chipR.pdf
R7 = RES_0: Part Number: WR04X1004FTL; Part type: Chip Resistor; Tolerance,Voltage,Dielectric,Lead Free(Y/N): +/-1%; Datasheet: \\172.29.17.1\cn\WLAN\WLAN2\boarddesignLIB\251_component_database\Datasheet\ResistorResistor_Walsin, chipR.pdf
R9 = RES_0: +/-1%; Manufacturer: WALSIN; Part Number: WR04X3003FTL; Datasheet: \\172.29.17.1\cn\WLAN\WLAN2\boarddesignLIB\241_component_database\Datasheet\Resistor\Resistor_Walsin_chipR.pdf
R10 = RES_0: +/-1%; Manufacturer: WALSIN; Part Number: WR04X1503FTL; Datasheet: \\172.29.17.1\cn\WLAN\WLAN2\boarddesignLIB\231_component_database\Datasheet\Resistor\Resistor_Walsin_chipR.pdf
R11 = RES_0: +/-1%; Manufacturer: WALSIN; Part Number: WR04X1203FTL; Datasheet: \\172.29.17.1\cn\WLAN\WLAN2\boarddesignLIB\228_component_database\Datasheet\Resistor\Resistor_Walsin_chipR.pdf
R20 R260 R261 = RES_0: Part Number: WR04X1002 FTL; Part type: Chip Resistor; Tolerance,Voltage,Dielectric,Lead Free(Y/N): +/-1%; Datasheet: \\172.29.17.1\cn\WLAN\WLAN2\boarddesignLIB\190_component_database\Datasheet\ResistorResistor_Walsin_chipR.pdf
R22 = RES_0: +/-1%; Manufacturer: WALSIN; Part Number: WR04X8062FTL; Datasheet: \\172.29.17.1\cn\WLAN\WLAN2\boarddesignLIB\01_component_database\Datasheet\Resistor\Resistor_Walsin_chipR.pdf
R23 = RES_0: +/-5%; Manufacturer: WALSIN; Part Number: WR04X104JTL; Datasheet: \\172.29.17.1\cn\WLAN\WLAN2\boarddesignLIB\01_component_database\Datasheet\Resistor\Resistor_Walsin_chipR.pdf
R29 R30 = RES_0: Part Number: WR04X1202FTL; Part type: Chip Resistor; Tolerance,Voltage,Dielectric,Lead Free(Y/N): +/-1%; Datasheet: \\172.29.17.1\cn\WLAN\WLAN2\boarddesignLIB\193_component_database\Datasheet\Resistor\Resistor_Walsin_chipR.pdf
R194 = RES_0: +/-1%; Manufacturer: WALSIN; Part Number: WR04X5102FTL; Datasheet: \\172.29.17.1\cn\WLAN\WLAN2\boarddesignLIB\01_component_database\Datasheet\Resistor\Resistor_Walsin_chipR.pdf
R195 = RES_0: +/-1%; Manufacturer: WALSIN; Part Number: WR04X7502FTL; Datasheet: \\172.29.17.1\cn\WLAN\WLAN2\boarddesignLIB\01_component_database\Datasheet\Resistor\Resistor_Walsin_chipR.pdf
R269 = RES_0: +/-1%; Manufacturer: WALSIN; Part Number: WR04X1001FTL; Datasheet: \\172.29.17.1\cn\WLAN\WLAN2\boarddesignLIB\01_component_database\Datasheet\Resistor\Resistor_Walsin_chipR.pdf
R275 = RES_0: Part Number: WR04X222 JTL; Part type: Chip Resistor; Tolerance,Voltage,Dielectric,Lead Free(Y/N): +/-5%; Datasheet: \\172.29.17.1\cn\WLAN\WLAN2\boarddesignLIB\164_component_database\Datasheet\ResistorResistor_Walsin, chipR.pdf
R525 = RES_0: +/-1%; Manufacturer: WALSIN; Part Number: WR04X1004FTL; Datasheet: \\172.29.17.1\cn\WLAN\WLAN2\boarddesignLIB\01_component_database\Datasheet\Resistor\Resistor_Walsin_chipR.pdf
U1 = SY8121C1ABC: 2A Load Current, 1.2MHz Switching Freq; Part Type: DCDC; Datasheet: \\172.29.17.1\cn\WLAN\WLAN2\boarddesignLIB\01_component_database\Datasheet\Power Supply ChipDCDC_Silergy, AN_SY8121C1.pdf
U2 = PL2303GC_QFN: USB to RS232,RS422,RS485, 16 GPIO pins can be used; Part Number: PL2303G4FIG7P2; Part Type: USB IC; Datasheet: \\172.29.17.1\cn\WLAN\WLAN2\boarddesignLIB\01_component_database\Datasheet\Communicaton Interface Chip\USB2UART_Prolific_PL2303GC
U4 = G9141: Dropout Voltage is 800mV @ 600mA Load; Manufacturer: GMT; Part Number: G9141T11U; Datasheet: \\172.29.17.1\cn\WLAN\WLAN2\boarddesignLIB\01_component_database\Datasheet\Power Supply Chip\LDO_GMT_EDS-9141.pdf
U5 = UMH3N: 2个NPN-预偏置 100mA 50V; Part Type: NPN-BJT; Datasheet: \\172.29.17.1\cn\WLAN\WLAN2\boarddesignLIB\01_component_database\Datasheet\Triode-MOS Tube-Transistor\NPN-BJT_ROHM, UMH3NTN.pdf
U29 = CP2102N_QFN: USB to RS232,RS422,RS485, 16 GPIO pins can be used; Manufacturer: Silicon Labs; Part Number: CP2102N; Datasheet: \\172.29.17.1\cn\WLAN\WLAN2\boarddesignLIB\01_component_database\Datasheet\Communicaton Interface Chip\USB2UART_Silicon Labs_CP2102N-A02-GQFN24R_规格书_WJ339251.pdf
USB1 = USB_TYPE_A_F0: TYPE-A母头
C58 = CAPACITOR_NON-POL_0: +/-0.1pF,25V,NPO,Y; Manufacturer: WALSIN; Part Number: RF03N0R9B250CT; Voltage: 25V; Datasheet: \\172.29.17.1\cn\WLAN\WLAN2\boarddesignLIB\26_component_database\Datasheet\Capacitor\Capacitor_Walsin_MLCC.pdf
C59 = CAPACITOR_NON-POL_0: Part Number: RF03N0R3B250CT; Part Type: Ceramic; Tolerance,Voltage,Dielectric,Lead Free(Y/N): +/-0.1pF,25V,NPO,Y; Datasheet: \\172.29.17.1\cn\WLAN\WLAN2\boarddesignLIB\12_component_database\Datasheet\Capacitor\Capacitor_Walsin_MLCC.pdf
C60 = Inductor_RF: ±0.3nH,15min; Manufacturer: TAIYO YUDEN; Part Number: HKQ0603W2N8S-T
C61 C62 = CAPACITOR_NON-POL_0: Part Number: RF03N1R2B250CT; Part Type: Ceramic; Tolerance,Voltage,Dielectric,Lead Free(Y/N): +/-0.1pF,25V,NPO,Y; Datasheet: \\172.29.17.1\cn\WLAN\WLAN2\boarddesignLIB\31_component_database\Datasheet\Capacitor\Capacitor_Walsin_MLCC.pdf
D12 = UNI-DIRECTIONAL_ESD_0: RF用
R135 = CAPACITOR_NON-POL_0: +/-0.1pF,25V,NPO,Y; Manufacturer: WALSIN; Part Number: RF03N1R8B250CT; Voltage: 25V; Datasheet: \\172.29.17.1\cn\WLAN\WLAN2\boarddesignLIB\44_component_database\Datasheet\Capacitor\Capacitor_Walsin_MLCC.pdf
U8 = DPX_1: Manufacturer: ACX; Part Number: FLT18D24255171D-3271A; Datasheet: \\172.29.17.1\cn\WLAN\WLAN2\boarddesignLIB\01_component_database\Datasheet\RF Chip\DPX_ACX_DP1608-R2455DBR1_Preliminary_S-R00-N1823_1.pdf
U9 = TP_0: Micro Coaxial Connector,-40℃-105℃; Part Number: RFCSR-N3300-TP40; Part Type: RF Connector; Datasheet: \\172.29.17.1\cn\WLAN\WLAN2\boarddesignLIB\01_component_database\Datasheet\Connector\RF Connector_Argosy_RFCSR-N3300-TP40_APL_Realtek (2017-03-06).pdf
U10 = ANT_0: Antenna, GND

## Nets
GND: C1.2 C2.2 C3.2 C5.2 C6.2 C8.2 C9.2 C15.2 C16.2 C17.2 C18.2 C19.2 C20.2 C21.2 C22.2 C23.2 C25.1 C26.2 C28.2 C29.2 C30.2 C31.2 C32.1 C33.2 C34.2 C35.1 C36.1 C37.1 C38.1 C39.1 C40.1 C41.2 C42.2 C43.2 C44.2 C45.2 C46.2 C47.1 C48.1 C49.1 C50.1 C51.2 C52.2 C53.2 C54.2 C55.2 C56.2 C57.2 C58.2 C59.2 C60.2 C61.2 C62.2 C63.2 C64.2 C65.2 C66.2 C67.1 C69.2 C70.1 C71.2 C72.2 C73.2 C74.2 C75.2 C76.2 C77.2 C78.2 C79.2 C80.1 C81.2 C82.2 C83.2 C84.2 C85.2 C86.2 C87.2 C88.2 C89.2 C90.2 C91.2 C92.1 C93.2 C94.2 C95.2 C96.2 C97.2 C98.1 C99.2 C100.2 C101.1 C102.2 C103.2 C104.2 C220.1 C223.2 C248.1 C249.1 C250.1 C251.1 C252.2 C253.2 C254.1 C255.2 CON1.1(GND) CON1.8(GND) CON1.9(GND) CON1.16(GND) CON3.6 CON3.10 CON3.12(GND1) CON3.13(GND2) CON3.14(GND3) CON3.15(GND4) D1.1 D2.1 D3.2 D4.2 D5.2 D6.1 D7.2(CATHODE) D12.2 D13.2 D14.2 FPC1.1 FPC1.11(GND) FPC1.12(GND) J2.1 J4.1 J11.1 J14.3 J14.4 J19.4 J23.1 J23.2 J24.1 J26.11 J26.12 R5.2 R6.2 R7.2 R10.2 R11.1 R23.2 R145.2 R154.2 R158.2 R165.2 R166.2 R167.2 R168.2 R172.1 R184.2 R190.1 R195.2 R261.2 R279.1 R523.2 R524.2 R525.2 R526.2 R527.2 R528.2 TVS1.3(C_cathode) U1.2(GND) U2.25(GND) U4.2(GND) U6.45(RFIN_A) U6.46(GND) U6.47(RFIN_G) U6.50(GND) U6.101(EPAD_GND) U7.2(GND) U7.4(GND) U8.2(GND) U8.4(GND) U8.6(GND) U9.2(G) U9.3(G) U10.2(GND) U11.33(EPAD) U12.2(GND) U13.2(GND) U29.25(EPAD) U31.4(GND) USB1.4(DGND) X1.2(GND) X1.4(GND)
GND_EARTH: C74.1 C75.1 C76.1 C77.1 C78.1 C79.1 CON2.8 CON2.S0(SHIELD0) CON2.S1(SHIELD1)
GND_LCDC: J20.6 J20.9 J20.14 J20.20 J20.25 J20.30 J20.34 J20.39 J21.1 J21.2 R523.1 R524.1 R526.1 R527.1 R528.1
VCC_CAN: C86.1 C87.1 C92.2 C248.2 R169.2 U12.3(VCC) U13.3(VCC)
VCC_SDIO: C97.1 C98.2 CON3.4 CON3.11 R179.2 R180.2
VDD_FLASH: C99.1 C100.1 R185.1 R186.1 R189.2 U31.8(VCC)
ANT: D12.1 R136.1 R137.2 U8.5(RFIO)
CANH0: J33.1 R270.1 U12.7(CANH)
CANH1: L3.3 R198.1 U13.7(CANH)
CANL0: J33.2 R271.1 U12.6(CANL)
CANL1: L3.2 R199.1 U13.6(CANL)
CC1: CON1.3(CC1) R5.1
CC2: CON1.11(CC2) R6.1
CHIP_EN: C90.1 D13.1 J13.1 J14.1 J14.2 R31.1 R65.2 U6.5(CHIP_EN)
DTR_N: R19.1 R30.2 R277.1 U5.1(E0)
LDOM_OUT: R123.2 R127.2 R196.1 R197.1
LDOM_OUT/PA0: C36.2 R123.1 R124.1 U6.2(LDOM_OUT__|__PA0)
LED_B: R204.2 R522.2
LED_G: R203.1 R521.2
LED_G1: CON2.9(D1) R157.1
LED_G2: C84.1 CON2.10(D2) R155.1
LED_R: R202.1 R520.2
LED_Y1: C85.1 CON2.12(D4) R156.1
LED_Y2: CON2.11(D3) R158.1
LX: L2.2 U6.100(LX)
PA2_UART_LOG_RXD: J5.1 R24.2 U6.6(PA2)
PA3: R35.1 R37.1 U6.7(PA3/TM_DIS)
PA3_PHY_RSTB: R37.2 R150.2 U11.21(PHYRSTB)
PA4: R39.1 R41.1 U6.10(PA4)
PA4_HSDP: R4.2 R41.2
PA5: R43.1 R45.1 U6.11(PA5)
PA5_HSDM: R3.2 R45.2
PA10: R55.1 R59.1 U6.16(PA10)
PA10_CAN_STB0: R59.2 R173.2
PA11: R63.1 R68.1 U6.17(PA11)
PA11_CAN_STB1: R63.2 R176.2
PA12_CAN_RX0: R75.2 U12.4(RXD)
PA12_EXT_CLK_OUT: C80.2 R72.1 R75.1 R152.2 U6.18(PA12)
PA13: R76.1 R77.1 U6.19(PA13)
PA13_CAN_TX0: R77.2 U12.1(TXD)
PA14: R78.1 R80.1 U6.20(PA14)
PA14_CAN_RX1: R80.2 U13.4(RXD)
PA15: R82.1 R84.1 U6.21(PA15)
PA15_CAN_TX1: R84.2 U13.1(TXD)
PA16: R86.1 R88.1 U6.22(PA16)
PA16_TOUCH4: FPC1.10 R88.2
PA17: R90.1 R91.1 U6.23(PA17)
PA17_TOUCH3: FPC1.9 R91.2
PA18: C57.1 R70.1 R92.1 R93.1 U6.27(PA18)
PA18_SDIO_CLK: C56.1 CON3.5 R70.2
PA18_TOUCH2: FPC1.8 R93.2
PA19: R69.1 R94.1 R95.1 U6.28(PA19)
PA19_SDIO_CMD: C55.1 CON3.3 R69.2
PA19_TOUCH1: FPC1.7 R95.2
PA20: R57.1 R96.1 R98.1 U6.29(PA20)
PA20_SDIO_D1: C53.1 CON3.8 R57.2
PA20_TOUCH0: FPC1.6 R98.2
PA21: R67.1 R100.1 R101.1 U6.30(PA21)
PA21_SDIO_D3: C54.1 CON3.2 R67.2
PA21_TOUCH8: FPC1.5 R101.2
PA22: R102.1 R103.1 U6.31(PA22)
PA22_TOUCH7: FPC1.4 R103.2
PA23: R104.1 R105.1 U6.32(PA23)
PA23_TOUCH6: FPC1.3 R105.2
PA24: R107.1 R108.1 U6.33(PA24)
PA24_TOUCH5: FPC1.2 R108.2
PA27: R47.1 R49.1 U6.36(PA27)
PA27_SDIO_D2: C51.1 CON3.1 R49.2
PA28: R51.1 R53.1 U6.37(PA28)
PA28_SDIO_D0: C52.1 CON3.7 R53.2
PA_0: J23.8 R124.2
PA_1: J23.6 R126.2
PA_3: J26.20 R35.2
PA_4: J26.19 R39.2
PA_5: J23.5 R43.2
PA_6: J20.26 U6.12(PA6)
PA_7: J20.27 U6.13(PA7)
PA_8: J20.28 U6.14(PA8)
PA_9: J20.32 R522.1 U6.15(PA9)
PA_10: J20.29 R55.2 R521.1
PA_11: J20.31 R68.2 R520.1
PA_12: J23.4 R72.2
PA_13: J20.36 R76.2
PA_14: J20.38 R78.2
PA_15: J20.40 R82.2
PA_16: J20.35 R86.2
PA_17: J20.33 R90.2
PA_18: J22.7 R92.2
PA_19: J22.8 R94.2
PA_20: J22.6 R96.2
PA_21: J23.3 R100.2
PA_22: J21.3 R102.2
PA_23: J21.4 R104.2
PA_24: J21.6 R107.2
PA_25: J21.5 U6.34(PA25)
PA_26: J21.8 U6.35(PA26)
PA_27: J22.4 R47.2
PA_28: J22.5 R51.2
PA_29: J21.7 U6.38(PA29)
PA_30: J22.3 U6.39(PA30)
PA_31: J22.2 U6.40(PA31)
PB3: R32.1 R34.1 U6.58(PB3)
PB3_DMIC_CLK: J19.1 R34.2
PB4: R36.1 R40.1 U6.59(PB4)
PB4_DMIC_DATA: J19.3 R40.2
PB18: R83.1 R85.1 U6.73(PB18/BOOT_NOR)
PB18_BOOT_NOR: R85.2 R182.2 R184.1
PB19: R87.1 R89.1 U6.74(PB19)
PB19_SDIO_CD: C251.2 CON3.9 R89.2
PB20_UART_LOG_TXD: D14.1 J6.2 J15.1 J15.2 R25.2 R171.1 U6.75(PB20/UD_DIS)
PB24: R46.1 R48.1 U6.80(PB24)
PB24_RMII_MDIO: R48.2 R146.1 U11.23(MDIO)
PB25: R50.1 R52.1 U6.81(PB25)
PB25_RMII_RXERR: R52.2 U11.28(RXER/FXEN)
PB26: R54.1 R56.1 U6.82(PB26)
PB26_RMII_CRS_DV: R56.2 U11.26(CRS/CRS_DV)
PB27_RMII_TXEN: R58.1 U6.83(PB27) U11.20(TXEN)
PB28: R60.1 R61.1 U6.84(PB28)
PB28_RMII_TXD1: R61.2 R529.1
PB29: R62.1 R64.1 U6.85(PB29)
PB29_RMII_TXD0: R64.2 R530.1
PB30_RMII_REF_CLK: R71.1 R147.1 U6.86(PB30)
PB31: R106.1 R200.1 U6.88(PB31)
PB31_RMII_RXD1: R106.2 R161.2 R168.1 R532.1
PB_0: J22.1 U6.41(PB0)
PB_3: J21.10 R32.2
PB_4: J21.9 R36.2
PB_5: J20.3 U6.60(PB5)
PB_6: J20.5 U6.61(PB6)
PB_7: J20.7 U6.62(PB7)
PB_8: J20.8 U6.63(PB8)
PB_9: J20.10 U6.64(PB9)
PB_10: J20.11 U6.65(PB10)
PB_11: J20.12 U6.66(PB11)
PB_12: J20.19 U6.67(PB12)
PB_13: J20.37 U6.68(PB13)
PB_14: J20.18 U6.69(PB14)
PB_15: J20.22 U6.70(PB15)
PB_16: J20.13 U6.71(PB16)
PB_17: J20.21 U6.72(PB17)
PB_18: J20.23 R83.2
PB_19: J23.7 R87.2
PB_21: J20.24 U6.77(PB21)
PB_22: J20.16 U6.78(PB22)
PB_23: J20.15 U6.79(PB23)
PB_24: J26.9 R46.2
PB_25: J26.10 R50.2
PB_26: J26.7 R54.2
PB_27: J26.8 R58.2
PB_28: J26.5 R60.2
PB_29: J26.6 R62.2
PB_30: J26.3 R71.2
PB_31: J26.4 R200.2
PC0: R109.1 R201.1 U6.89(PC0)
PC0_RMII_RXD0: R109.2 R533.1
PC1: R42.1 R44.1 U6.90(PC1)
PC1_RMII_MDC: R44.2 U11.22(MDC)
PC2_FLASH_D1: R110.1 U6.91(PC2) U31.2(SO/IO1)
PC3_FLASH_CS: R112.1 R186.2 U6.92(PC3) U31.1(\\~{C}S)
PC4_FLASH_D3: R114.1 R189.1 U6.93(PC4) U31.7(\\~{HOL}D/IO3)
PC5_FLASH_CLK: R116.1 U6.94(PC5) U31.6(SCLK)
PC6_FLASH_D0: R118.1 U6.95(PC6) U31.5(SI/IO0)
PC7_FLASH_D2: R120.1 R190.2 U6.96(PC7) U31.3(\\~{W}P/IO2)
PC_0: J26.1 R201.2
PC_1: J26.2 R42.2
PC_2: J26.13 R110.2
PC_3: J26.14 R112.2
PC_4: J26.15 R114.2
PC_5: J26.16 R116.2
PC_6: J26.17 R118.2
PC_7: J26.18 R120.2
PIN1: R12.1 U2.1(RXD) U29.1(RI/CLK)
PIN2: R279.2 U2.2(RI_N) U29.2(GND)
PIN3: R280.2 U2.3(TXEN) U29.3(D+)
PIN4: R281.2 U2.4(DSR_N) U29.4(D-)
PIN5: R282.2 U2.5(DCD_N) U29.5(VIO)
PIN6: R283.2 U2.6(CTS_N) U29.6(VDD)
PIN7: R284.2 U2.7(SUSP_N) U29.7(VREGIN)
PIN8: R285.1 U2.8(GPB3) U29.8(VBUS)
PIN9: R286.1 U2.9(GPB2) U29.9(RSTb)
PIN10: R15.1 U2.10(DP) U29.10(NC)
PIN11: R16.1 U2.11(DM) U29.11(GPIO.3/WAKEUP)
PIN12: R14.1 U2.12(VO_33) U29.12(GPIO.2/RS485)
PIN13: R272.1 U2.13(RESET_N) U29.13(GPIO.1/RXT)
PIN14: R13.1 U2.14(VIN) U29.14(GPIO.0/TXT)
PIN19: R276.1 U2.19(XI) U29.19(RTS)
PIN20: R278.1 U2.20(XO) U29.20(RXD)
PIN21: J5.2 R24.1 U2.21(TXD) U29.21(TXD)
PIN22: R19.2 U2.22(DTR_N) U29.22(DSR)
PIN23: R18.2 U2.23(RTS_N) U29.23(DTR)
PIN24: R17.1 R277.2 U2.24(VDD_IO) U29.24(DCD)
RFIO_A: R135.1 U6.44(RFIO_A)
RFIO_G: R134.1 U6.48(RFIO_G)
RMII_AVDD10: C72.1 U11.2(AVDD10OUT)
RMII_DVDD10: C71.1 U11.29(DVDD10OUT)
RMII_LED0_AD0/PMEB: R155.2 R163.2 R167.1 U11.24(LED0/PHYAD[0]/PMEB)
RMII_LED1_AD1: R156.2 R162.2 R166.1 U11.25(LED1/PHYAD[1])
RMII_MDI0+: R142.1 U11.3(MDI+[0])
RMII_MDI0-: R140.1 U11.4(MDI-[0])
RMII_MDI1+: R143.1 U11.5(MDI+[1])
RMII_MDI1-: R144.1 U11.6(MDI-[1])
RMII_PHY_AVDD33: C66.1 C69.1 R141.2 U11.7(AVDD33) U11.30(AVD33)
RMII_PHY_VDD: C63.1 C65.1 R139.2 R146.2 R149.1 R157.2 R159.1 R160.1 R161.1 R162.1 R163.1 U11.14(DVDD33)
RMII_RSET: R145.1 U11.1(RSET)
RMII_RXD0: R533.2 U11.9(RXD[0])
RMII_RXD1: R532.2 U11.10(RXD[1])
RMII_RXDV: R159.2 U11.8(RXDV)
RMII_TX_CLK_S: R531.2 U11.15(TXC)
RMII_TXD0: R530.2 U11.16(TXD[0])
RMII_TXD1: R529.2 U11.17(TXD[1])
RMII_XTAL1: R153.1 R154.1 U11.31(CKXTAL1)
RMII_XTAL2: R151.2 R289.1 U11.32(CKXTAL2)
RTS_N: R18.1 R29.1 R276.2 U5.4(E1)
RXD3/CLK_CTL: R160.2 R165.1 U11.12(RXD[3]/CLK_CTL)
UART_LOG_TX: J6.1 R12.2 R25.1 R28.2 R278.2
USB5V: C1.1 C2.1 C15.1 C249.2 C250.2 CON1.2(VBUS) CON1.7(VBUS) CON1.10(VBUS) CON1.15(VBUS) D5.1 R1.1 R13.2 R260.1 R284.1
USB5V_TYPEA: C253.1 C254.2 D1.2 R2.1 USB1.1(VCC)
USB_DN: CON1.5(DN1) CON1.13(DN2) D4.1 R16.2 R281.1
USB_DP: CON1.4(DP1) CON1.12(DP2) D3.1 R15.2 R280.1
VAH_RTC: C64.1 D10.1 D11.1 R122.2 R125.2 R133.2
VAH_RTC/PA1: C38.2 R125.1 R126.1 U6.4(VAH_RTC__|__PA1)
VD5V: C5.1 C6.1 C19.1 C20.1 J1.1 R1.2 R2.2 R169.1 R194.1 R288.1 U1.5(VIN) U4.1(IN) U4.3(~{SHDN})
VD5V_0: J20.2 J20.4 R288.2
VD09: C28.1 C30.1 C39.2 C40.2 U6.8(VAL_USB) U6.9(VDL_CORE) U6.87(VDL_CORE) U6.98(LDOC_OUT)
VD18: R21.2 R130.1 R132.1 R180.1
VD18_REG: C21.1 C22.1 R21.1 R22.1 U4.5(OUT)
VD33: J3.1 J7.1 R8.2 R139.1 R141.1 R170.1 R179.1 R191.1 R193.1 R275.1 R287.1 U30.2(VDD)
VD33_0: J20.1 J20.17 R193.2
VD33_DMIC: J19.2 R287.2
VD33_REG: C7.1 C8.1 C9.1 L1.2 R8.1 R9.1
VD33_WL: C31.1 C34.1 C35.2 C37.2 C42.1 C44.1 C48.2 C49.2 C50.2 C95.1 C96.1 C103.1 D10.2 J7.2 R26.2 R65.1 R122.1 R128.2 R129.1 R131.1 R171.2 R182.1 R185.2 R191.2 U6.1(VAH_DCDC) U6.3(VAH_LDOM) U6.24(VAH_ADC) U6.42(VRH_PAD_A) U6.43(VRH_PA_A) U6.49(VRH_PA_G) U6.52(VRH_SYN) U6.56(VAH_XTAL) U6.76(VDH_IO2)
VD125: C29.1 C32.2 C33.1 C41.1 C43.1 C46.1 L2.1 U6.51(VRM_RF) U6.53(VRM_SYN) U6.57(VAM_AFE) U6.99(VAM_LDOC)
VDH_IO0: C45.1 R129.2 R130.2 R196.2 U6.25(VDH_IO0)
VDH_IO1: C47.2 R131.2 R132.2 R197.2 U6.26(VDH_IO1)
VDM_PSRAM/VDH_FLASH: C26.1 R127.1 R128.1 U6.97(VDM_PSRAM__|__VDH_FLASH)
VIO: C23.1 R17.2 R26.1 R27.1 R282.1
VIO_CAN: C88.1 C89.1 C93.1 C104.1 R170.2 U12.5(VIO) U13.5(VIO)
VO33: C17.1 C18.1 C220.2 C223.1 R14.2 R20.2 R27.2 R269.2 R283.1
XI: U6.54(XI) U7.1(XTALP)
XO: U6.55(XO) U7.3(XTALP)
N16769979: C25.2 R31.2 U5.3(C1)
N16770039: R28.1 U5.6(C0)
N16770049: R30.1 U5.5(B1)
N16770085: R29.2 U5.2(B0)
N16770201: C7.2 R9.2 R10.1 R11.2 U1.3(FB)
N16770807: C4.2 L1.1 U1.6(LX)
N16770811: C4.1 U1.1(BS)
N16771457: C3.1 CON1.17(PAD) CON1.18(PAD) CON1.19(PAD) CON1.20(PAD) R7.1
N16780191: C59.1 R136.2 U9.1(Feed)
N16780217: C61.1 R137.1 R138.1
N16780233: C62.1 R138.2 U10.1(FEED)
N16782603: J15.3 J15.4 R172.2
N16870954: D11.2 J10.1 R133.1
N17023005: C60.1 R135.2 U8.3(5G)
N17023115: C58.1 R134.2 U8.1(2G)
N17167501: D6.2 R3.1 USB1.2(D-)
N17167505: D2.2 R4.1 USB1.3(D+)
N17173023: C73.1 C255.1 R147.2 R531.1
N17176002: C83.1 R151.1 X1.3(XTALP)
N17176031: C82.1 R153.2 X1.1(XTALP)
N17178495: CON2.1(TD+) R142.2
N17178497: CON2.2(TD-) R140.2
N17178499: CON2.3(RD+) R143.2
N17178501: CON2.6(RD-) R144.2
N17178524: C67.2 CON2.4(TCT)
N17178526: C70.2 CON2.5(RCT)
N17227452: R173.1 U12.8(STB)
N17227975: R176.1 U13.8(STB)
N17282094: C81.1 R149.2 R150.1
N17289901: R22.2 R23.1 U4.4(SET)
N17306341: R194.2 R195.1 U1.4(EN)
N17324429: C101.2 J17.1 L3.4 R198.2 R399.1 TVS1.2(Cathode)
N17324430: C102.1 J17.2 L3.1 R199.2 R400.1 TVS1.1(Cathode)
N17343293: R260.2 R261.1 R285.2
N17348259: R269.1 R286.2
N17354107: D7.1(ANODE) R275.2
N17355494: C16.1 R20.1 R272.2
N17390445: C94.1 R270.2 R271.2
N17390719: C91.1 R399.2 R400.2
N17409065: R152.1 R289.2
N17456420: R204.1 U30.4(Blue)
N17456422: R202.2 U30.1(Red)
N17456424: R203.2 U30.3(Green)
N17492011: C252.1 R525.1 USB1.5(SHLD) USB1.6(SHLD)

Not connected (* = marked no-connect by the designer): CON1 6(SBU1)* 14(SBU2)*; CON2 7(N/A)*; H1 1*; H2 1*; H3 1*; H4 1*; U2 15(GPB0)* 16(GPB1)* 17(GPB4)* 18(GPB5)*; U11 11(RXD[2]/INTB)* 13(RXC)* 18(TXD[2])* 19(TXD[3])* 27(COL)*; U29 15(SUSPENDb)* 16(NC)* 17(SUSPEND)* 18(CTS)*

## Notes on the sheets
sheet 1
- Block Diagram
- Diplexer
- SD card
- GPIO
  Pin Header
- RMII
- Captouch
- LCD
- CAN
- Main IC
  QFN100
- CTC/ADC
- USB
- XTAL
- USB2UART
- USB
- DCDC/LDO
- Flash
sheet 2
- Power Tree
- USB TypeC
- 5V
- USB to UART
- System Power Option 3.3V
- 1.8V
- 1.8V
- micro SD socket
   or IO pins(1.8V)
- 5V
- DCDC or LDO
  5V to 3.3V or 1.8V
- 3.3V
- 3.3V_WL
- USB TYPE-A
- LDOM
  (1.8V)
- 1.8V
- Power Supply
  40Pin Header J20
- 5V
- SWR
  (1.25V)
- 1.25V
- LDOC
  (0.9V)
- 0.9V
- for 0.9V pins
- for 1.25V pins
- for 1.8V pins
- for 3.3V pins
- other blocks
sheet 3
- USB Type-C
- USB Type-A
- +5V to +3.3V DCDC
- 4.2V to 18V
- USB to UART(PL2303)
- Vout=0.6*[1+300/(150//120)]=3.3V
- +5V to +1.8V LDO  RSVD
- Vout=1*(1+80.6/100)=1.806V
- Auto Download
- USB to UART(CP2102) RSV
- Power Indicator
- Hole
sheet 4
- Pin Mux
- Main Chip
- PIN 7 is the TM_DIS trap pin,
  which must be kept at a high
  level during power on
- xtal
- CL=9pF
- Part Number Option
- IO Power Options
- Reserved for RTC function
- Depending on the specific IC,
  different components are required.
- RTL8721FLM
- RTL8721FLF
- R123
- Placed near main IC
  Reserved for filtering SDIO  interference to WiFi
- R124
- R125
- R126
- R127
- R128
- Power from battery
sheet 5
- RF
- Colay
- Reserved for ESD
- PCB ANT
- PI matching for ANT
sheet 6
- Ethernet
- RJ45 Interface
- Note:
  1.Cap for RMII_PHY_AVDD33  must closed to 8201F
  pin7&30(Analog)
  2.Cap for RMII_PHY_VDD must closed to 8201F
  pin14(digital)
- Note:
  1.Cap for DVDD10 must be closed to 8201F pin29
  2.Cap for AVDD10 must be closed to 8201F pin2
- Note:
  1.R147&C73 must be closed to main IC
  RTL8721FL
  2.C255 must be closed to 8201F pin15
- R529&R530&R531&R532&R533 must be closed to main IC  RTL8721FL
- Clock Option (XTAL/External CLK)
- RESET
- CLK_OP1
- CLK_OP2(default)
- Please mount R149 if MAC_RST(MAC site) can not
  weak pull high.
  PHYRSTB Pin connect to MAC.
  Please reference the datasheet section 9.1.3
  Power on and PHY reset sequence
- LED
- 100M Link/Receive/Transmit
- R152&C80 must be closed to main IC RTL8721FL
- 10M Link/Receive/Transmit
- Function configuration
- WOL/PHY ADDR
- LED0/PMEB pin is 5V tolerance
  Avaliable PHY address (8201F):
  (1)Default:  0x00000~0x00011
  (2)LED mode(RXD1=0):
  0x00000~0x00011
  (3)WOL mode(RXD1=1) : 0x00001
  or 0x00011
  LED_AD1/LED_AD0 :
  L/L = 00
  L/H = 01(default)
  H/L = 10
  H/H = 11
- Note1 : LED need to drive by VDD33 with 510 ohm current limit resistor.
  Note2 : LED0/PMEB and LED1 pins are 5V tolerance.
  Note2:  LED1_AD1/LED0_AD0=01(default)
- Pull High: RMII mode
- Pull Low: Output mode
  Pull High: Input mode(default)
- Pull Low: LED mode
  Pull High: WOL mode
  default internal pull low
sheet 7
- Chip_EN Button
- Download Button
- CAN
- CAP Touch Connector
- Micro SD socket
- DMIC PIN Header
- Power trap
- User LED
- External Flash
- Flash NC for MainIC_MCM_flash
  Flash Placed for MainIC_MCM_psram
- Flash type
  1: NOR
  0: NAND
sheet 8
- 40PIN Header
- SDIO_CLK
- SDIO_D3
- SDIO_CMD
- SDIO_D0
- SPI_MOSI
- SPI_MISO
- SDIO_D1
- SPI_CLK
- SPI_CS
- SDIO_D2
- PIN Header
